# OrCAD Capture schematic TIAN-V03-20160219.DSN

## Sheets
1 03_MIPS_76K_CPU: size A; title: 03_MIPS_76K_CPU; rev: 03; note: Tian
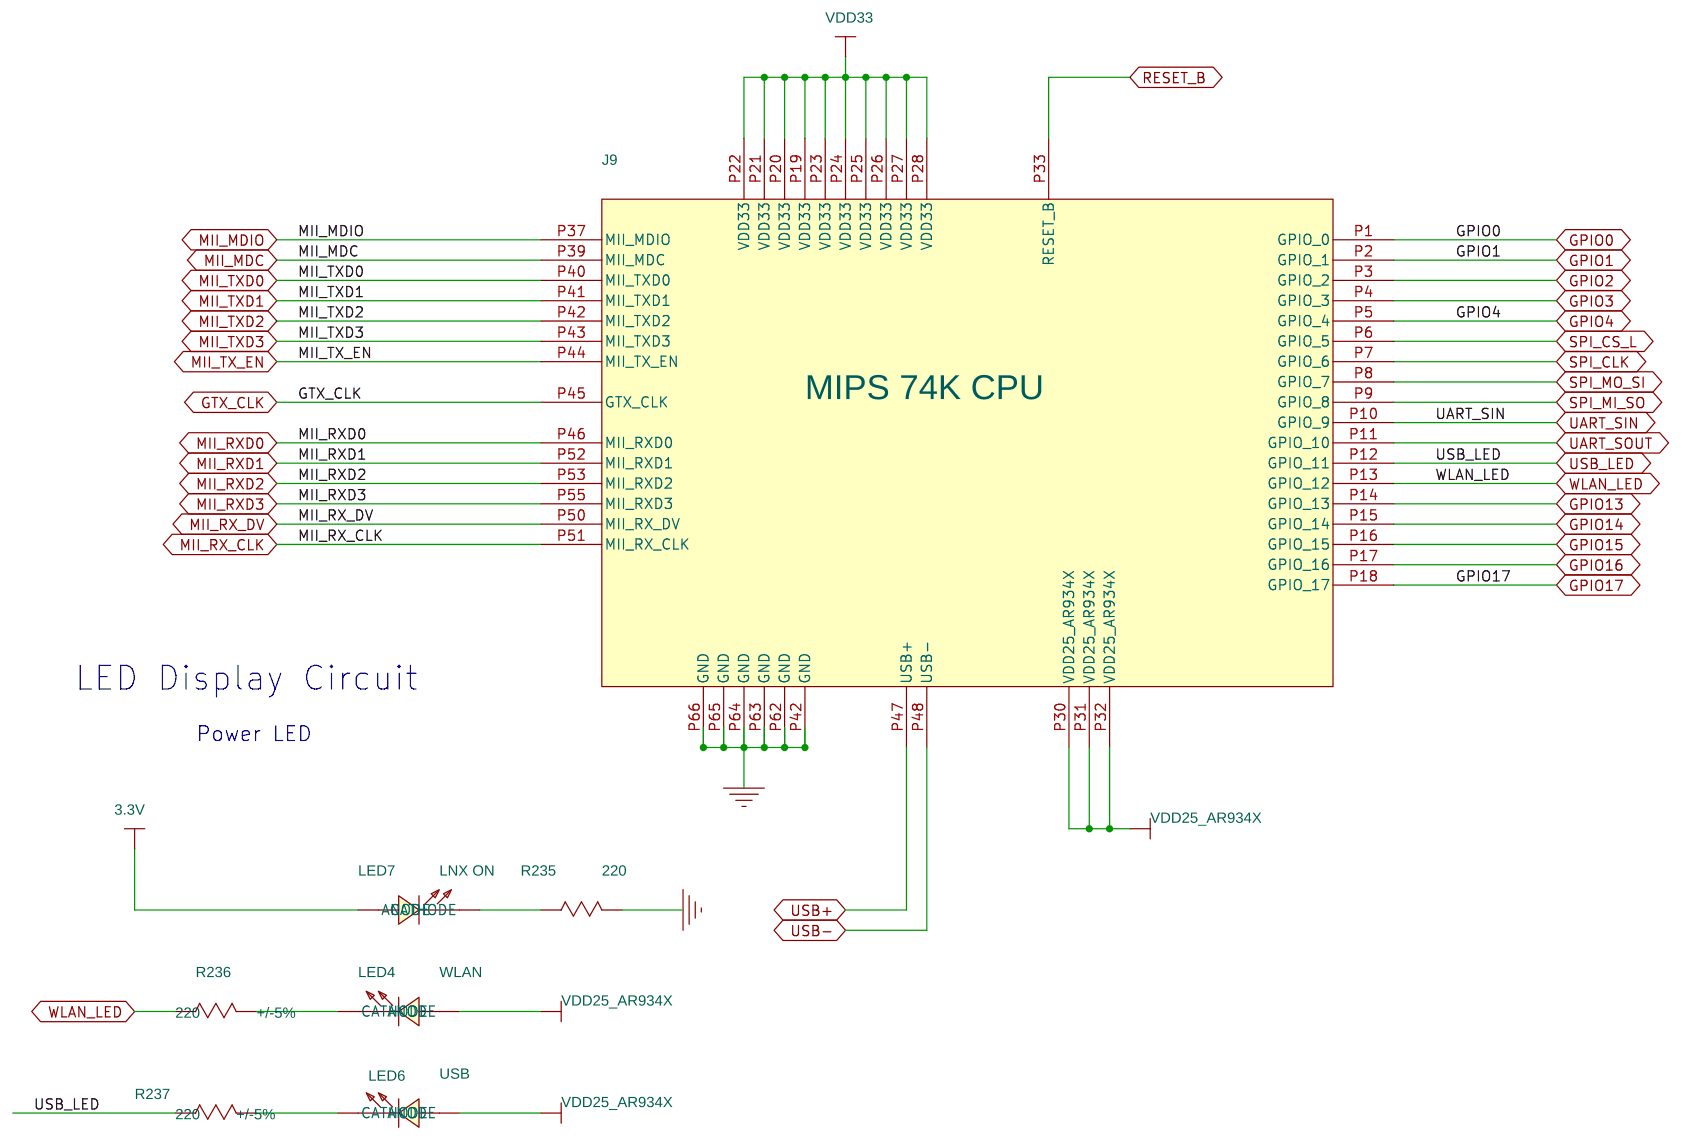
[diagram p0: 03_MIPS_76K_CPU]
2 01_Block_Diagram: title: 01_Block Diagram
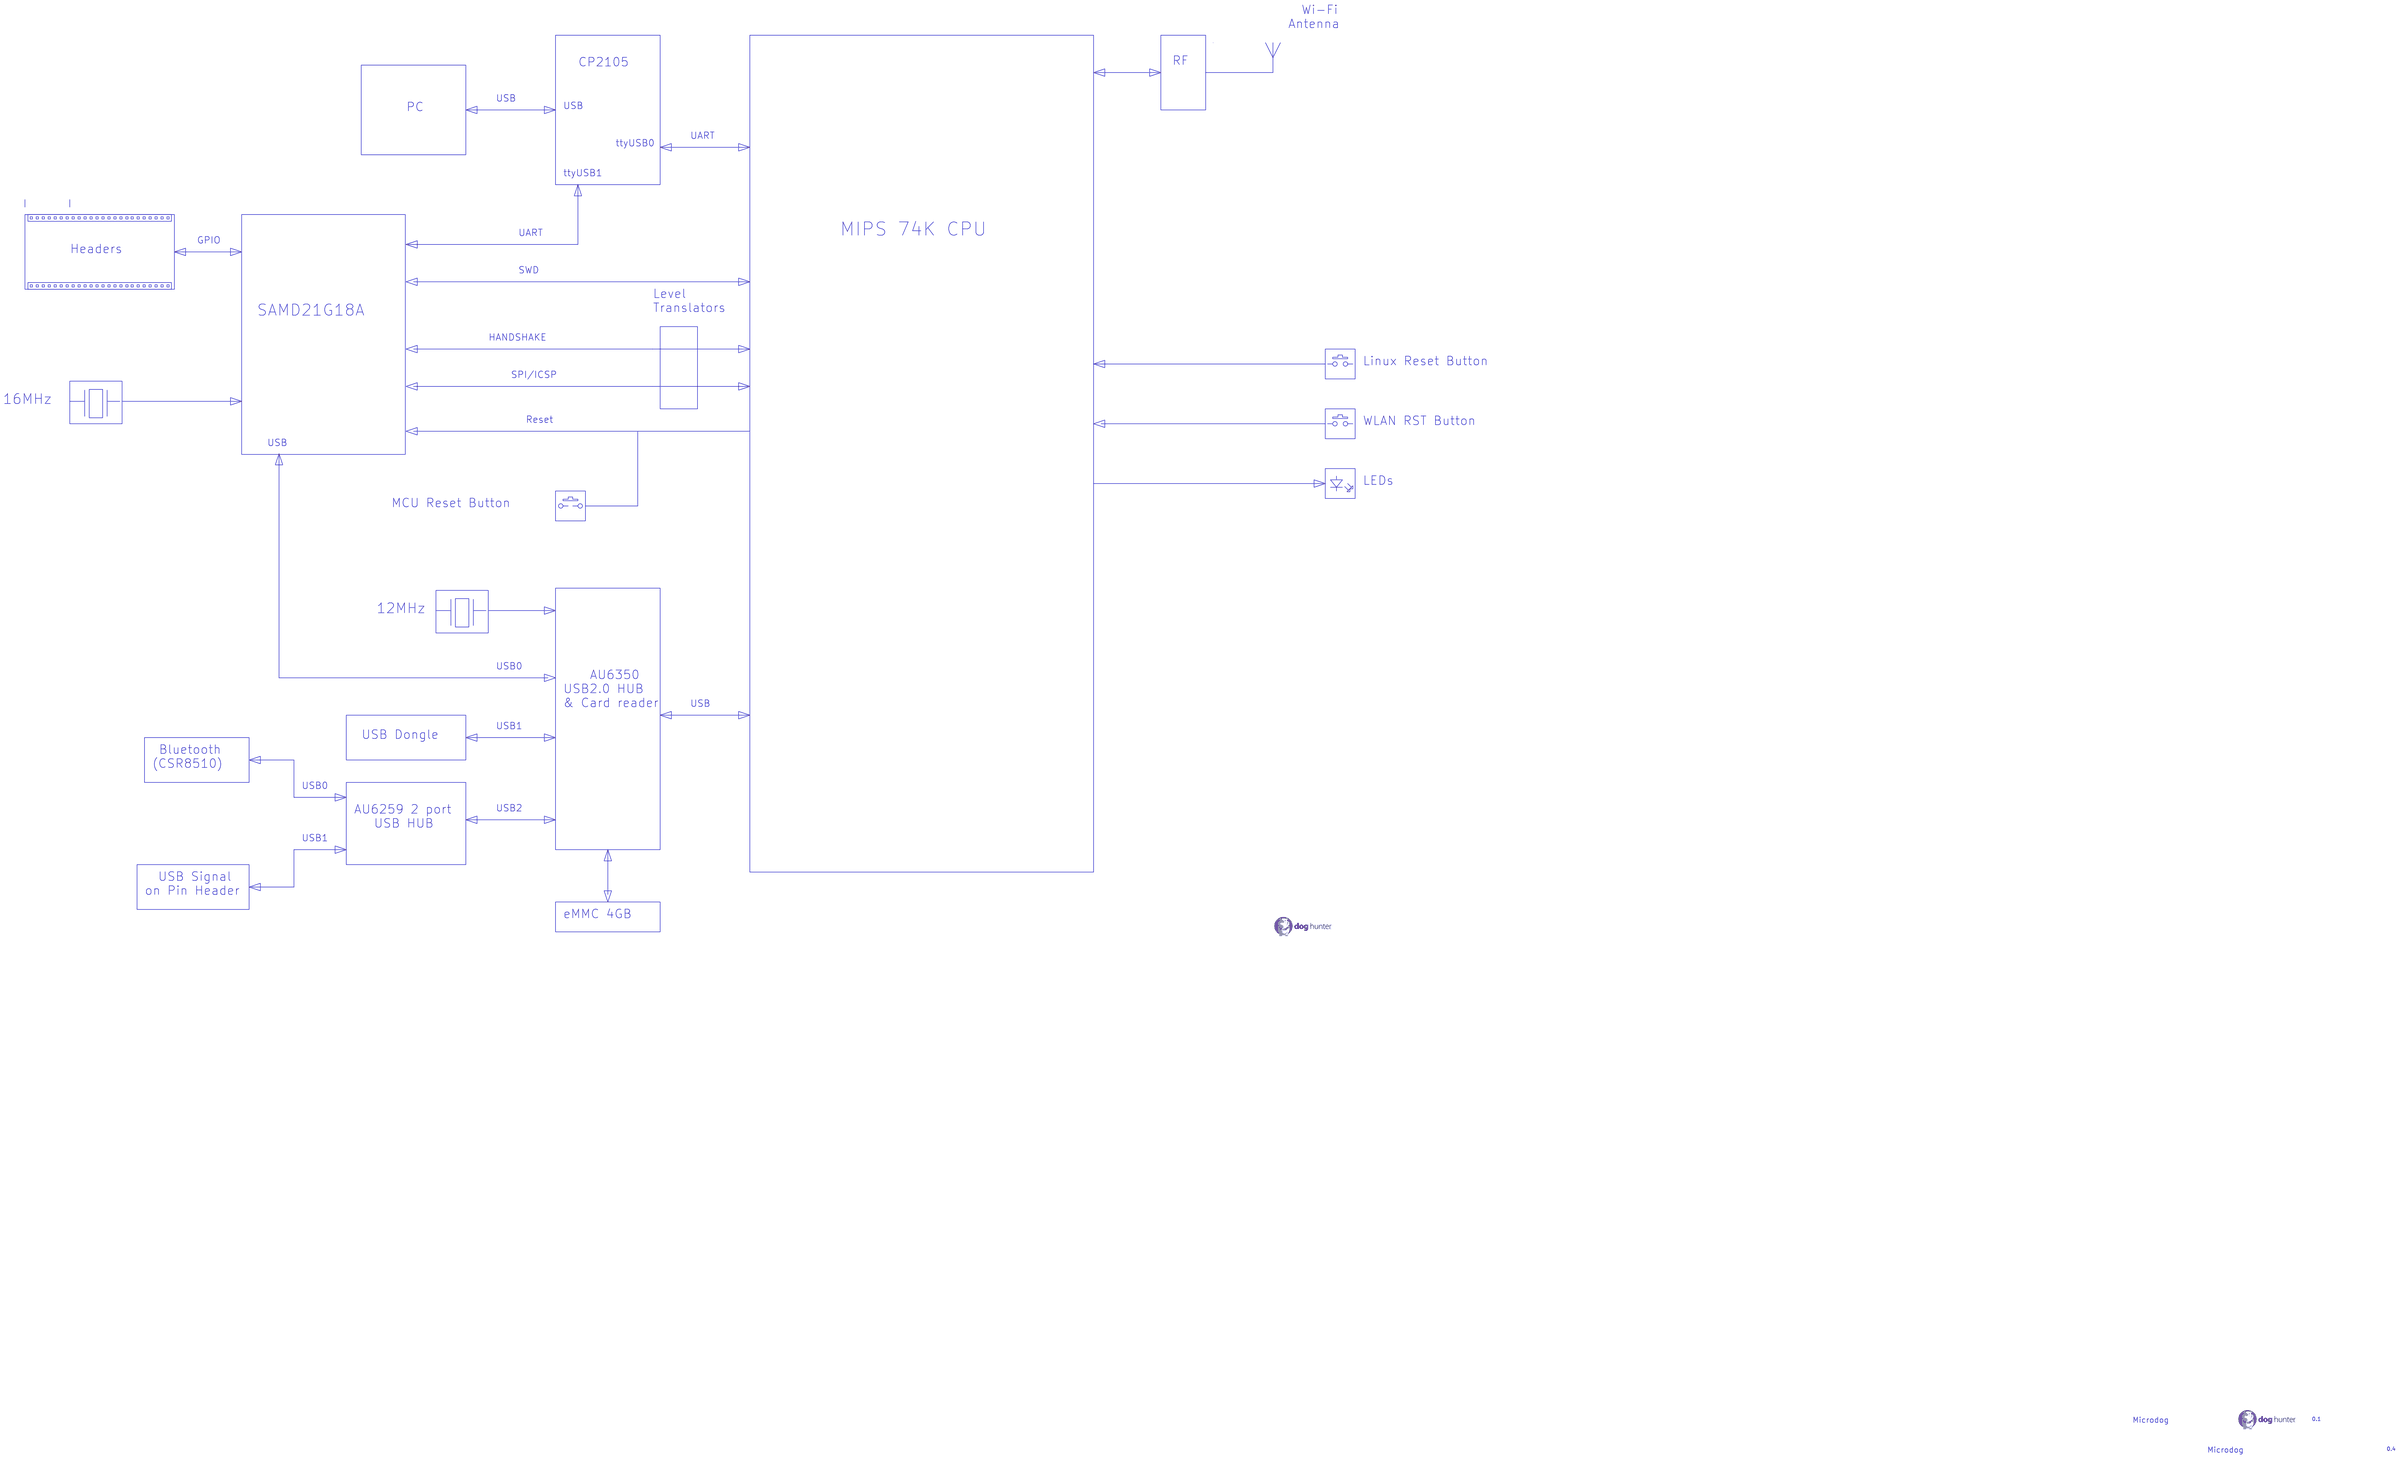
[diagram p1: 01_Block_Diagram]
3 02_Power_Block_Diagram: size A3; title: 02_Power Block Diagram
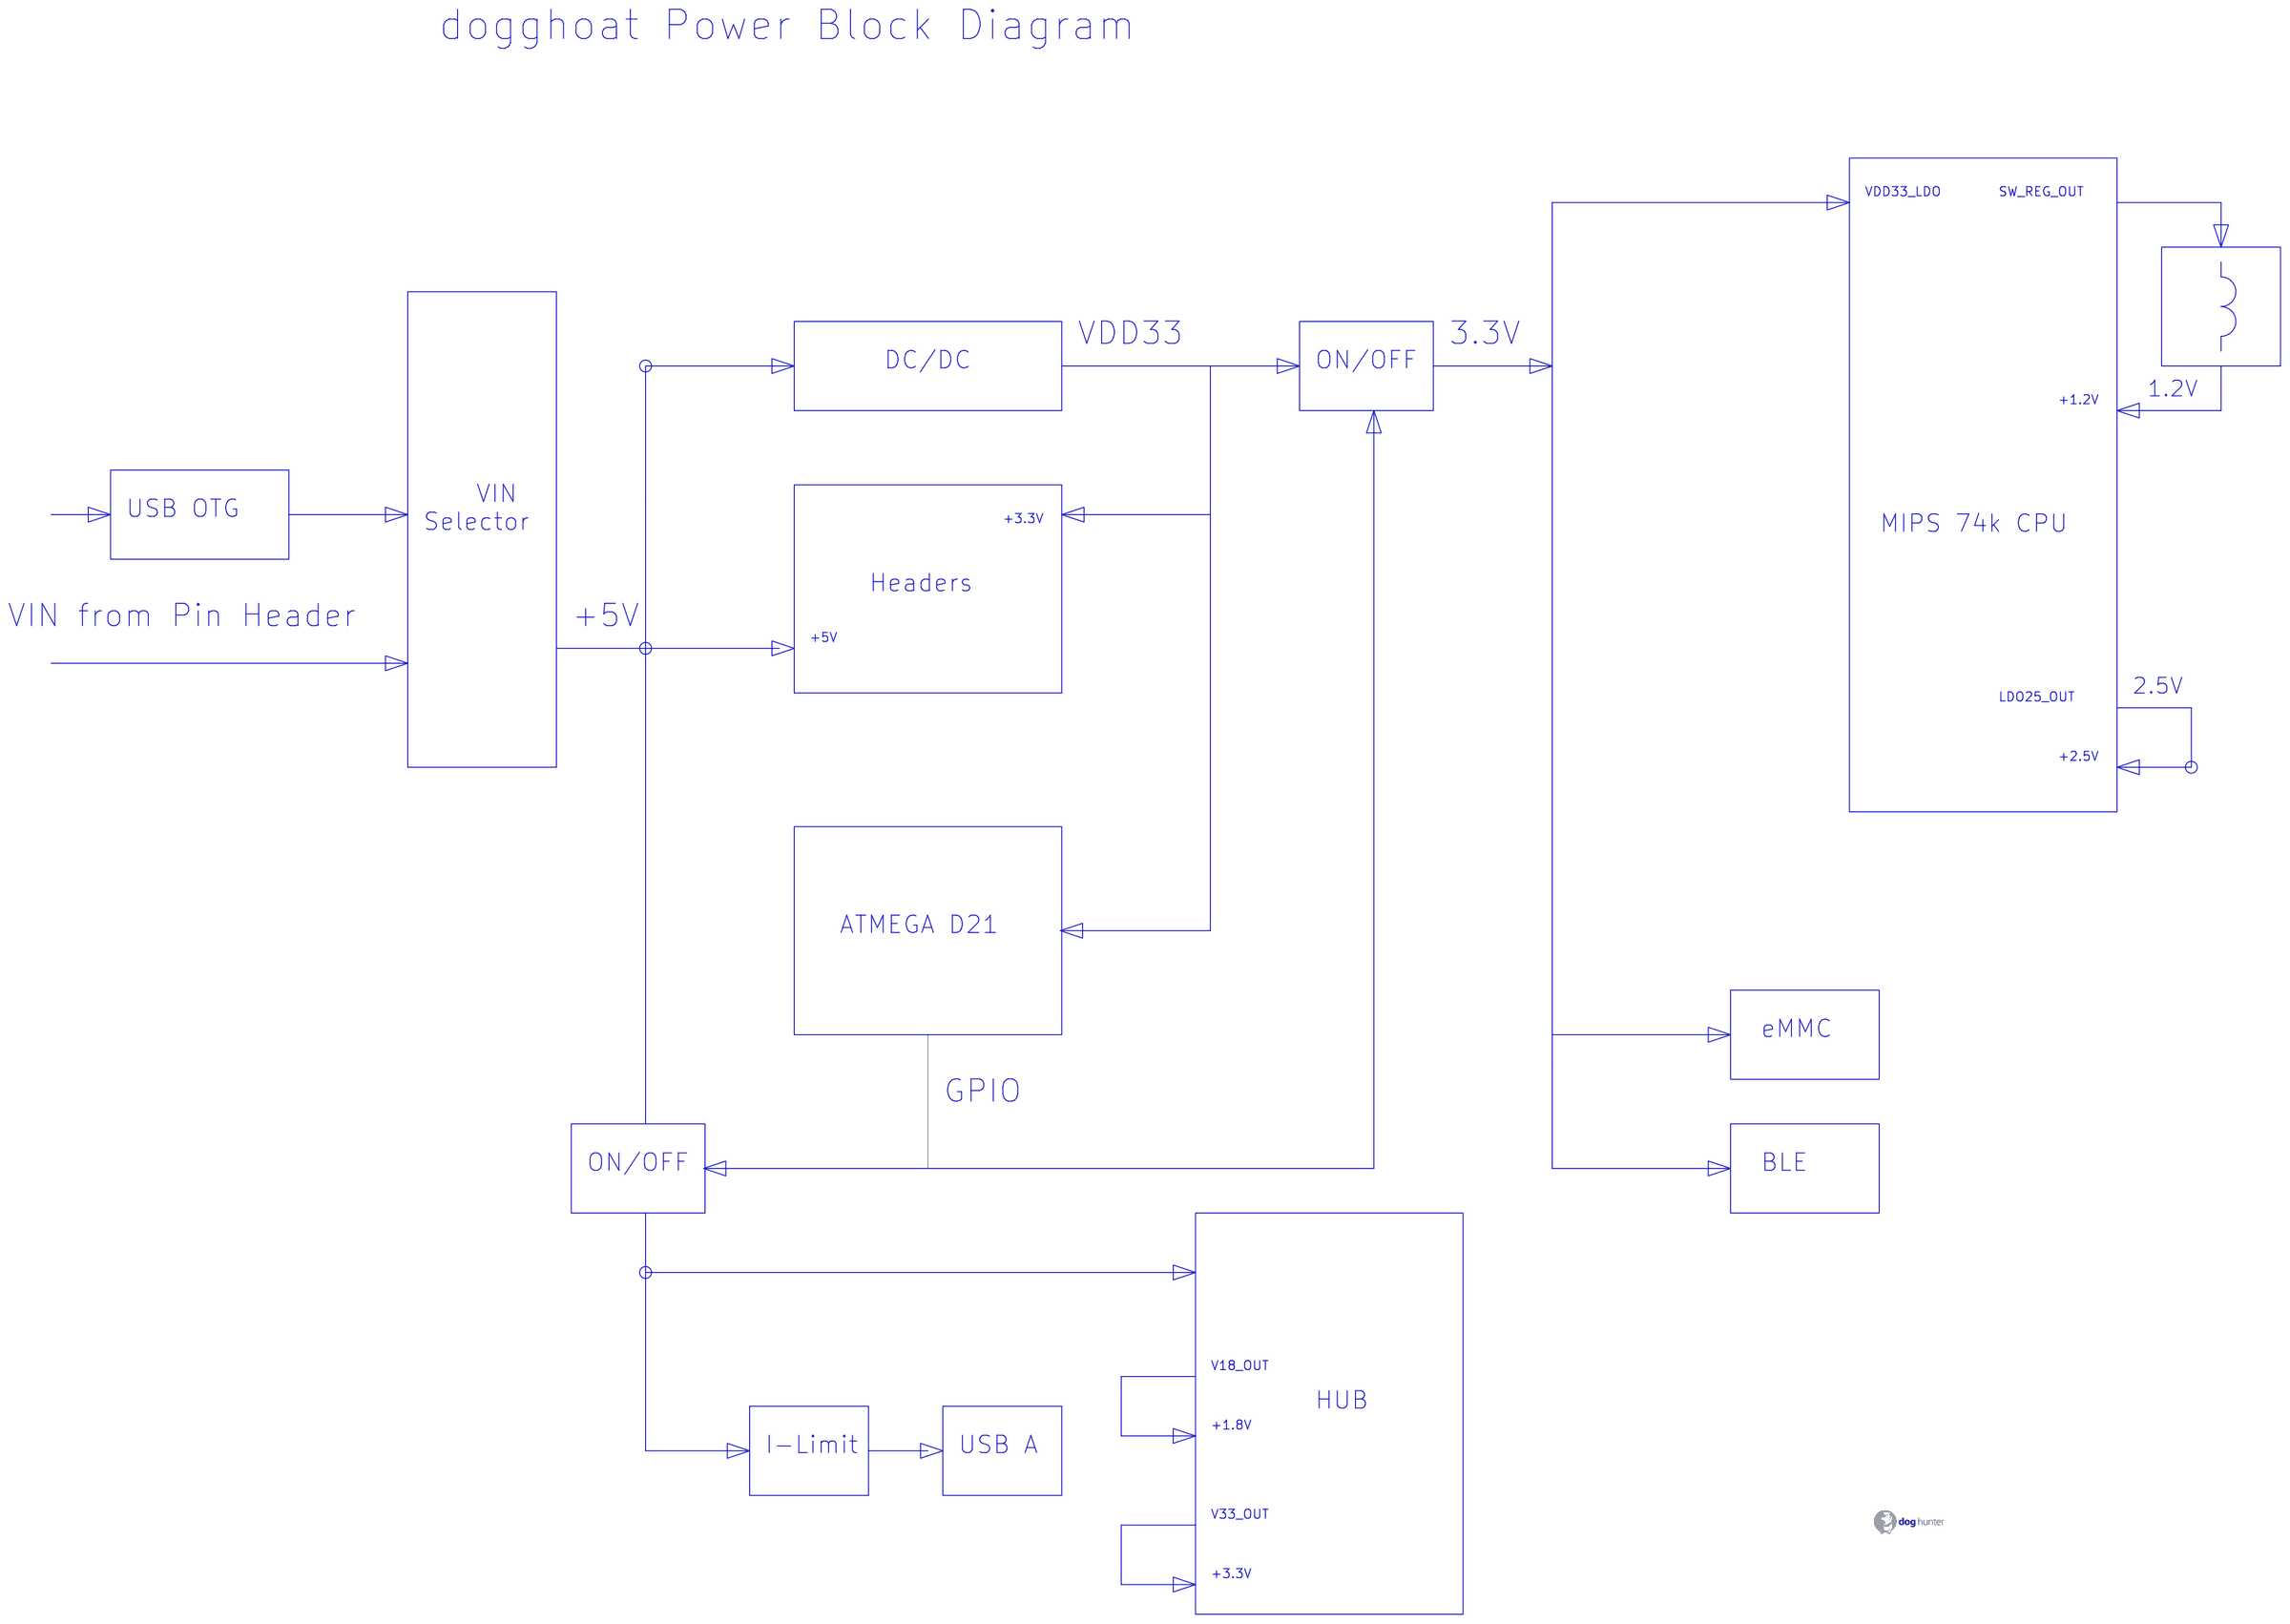
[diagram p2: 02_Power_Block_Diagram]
4 06_UART_EJTAG_USB_PWR_FLASH: size C; title: 06_UART_EJTAG_USB_PWR_FLASH
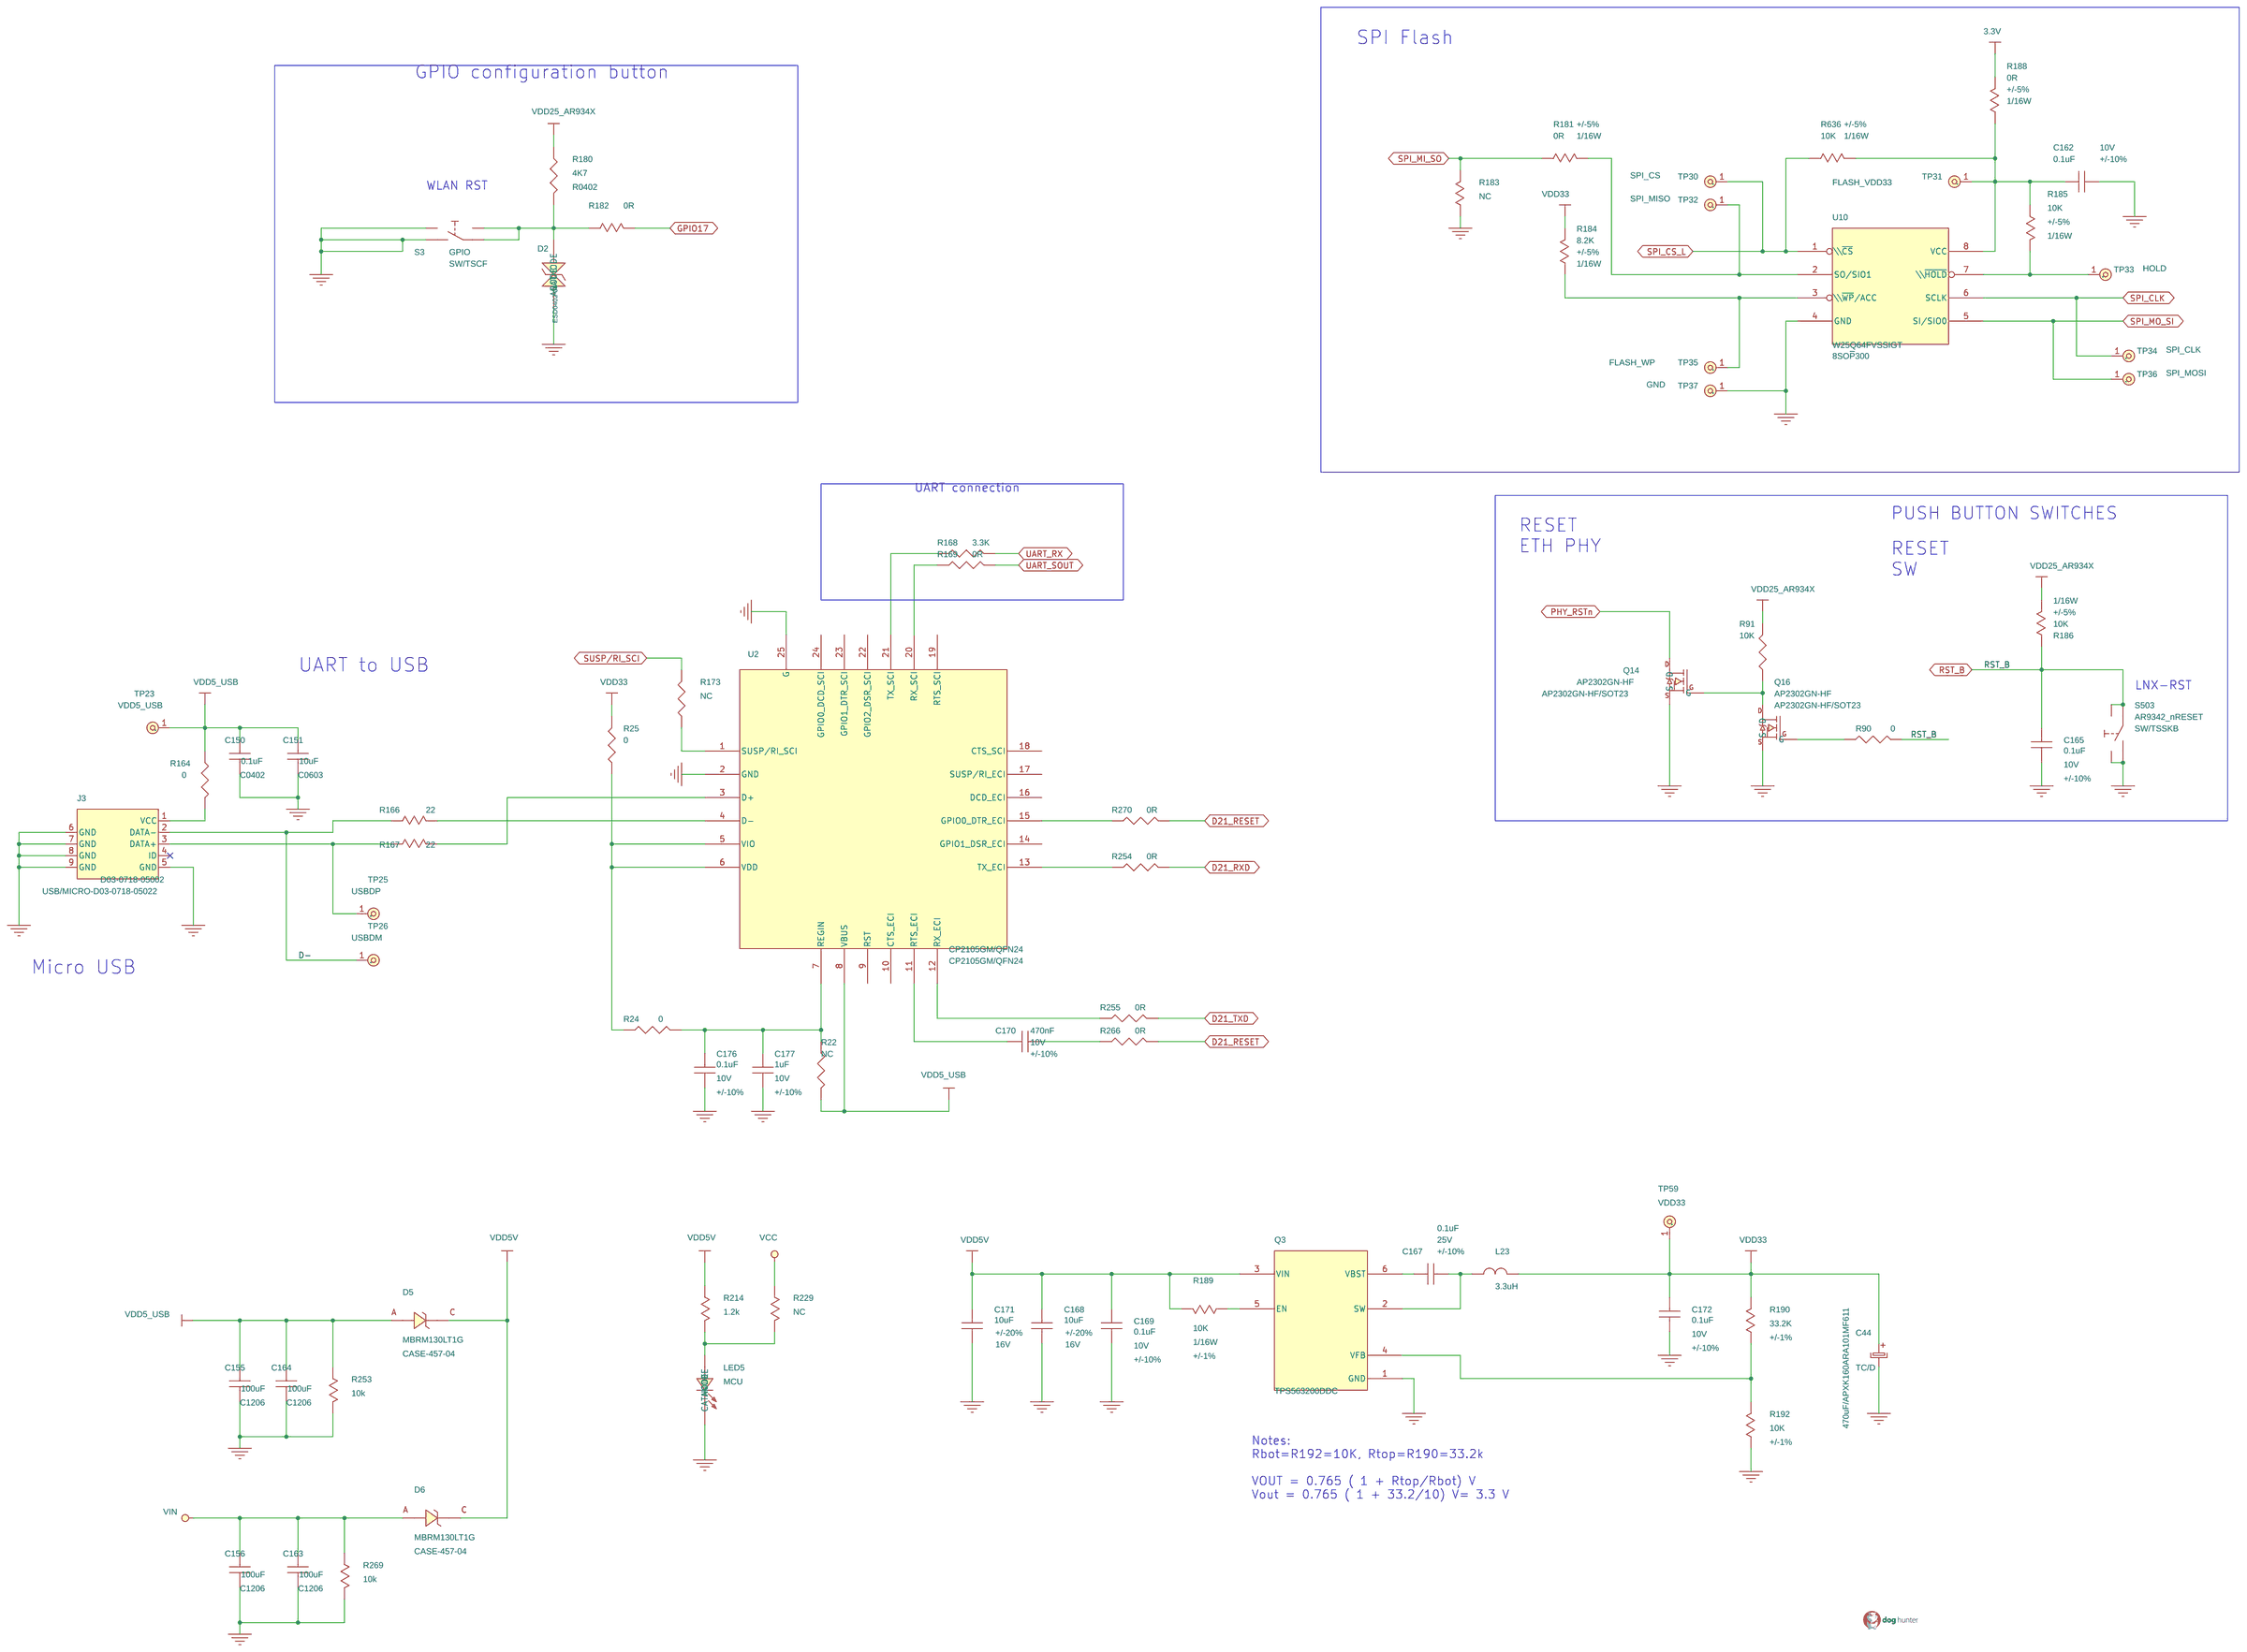
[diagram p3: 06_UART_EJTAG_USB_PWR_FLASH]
5 07_Ethernet_PHY_AR8035: size C; title: 07_Ethernet_PHY_AR8035
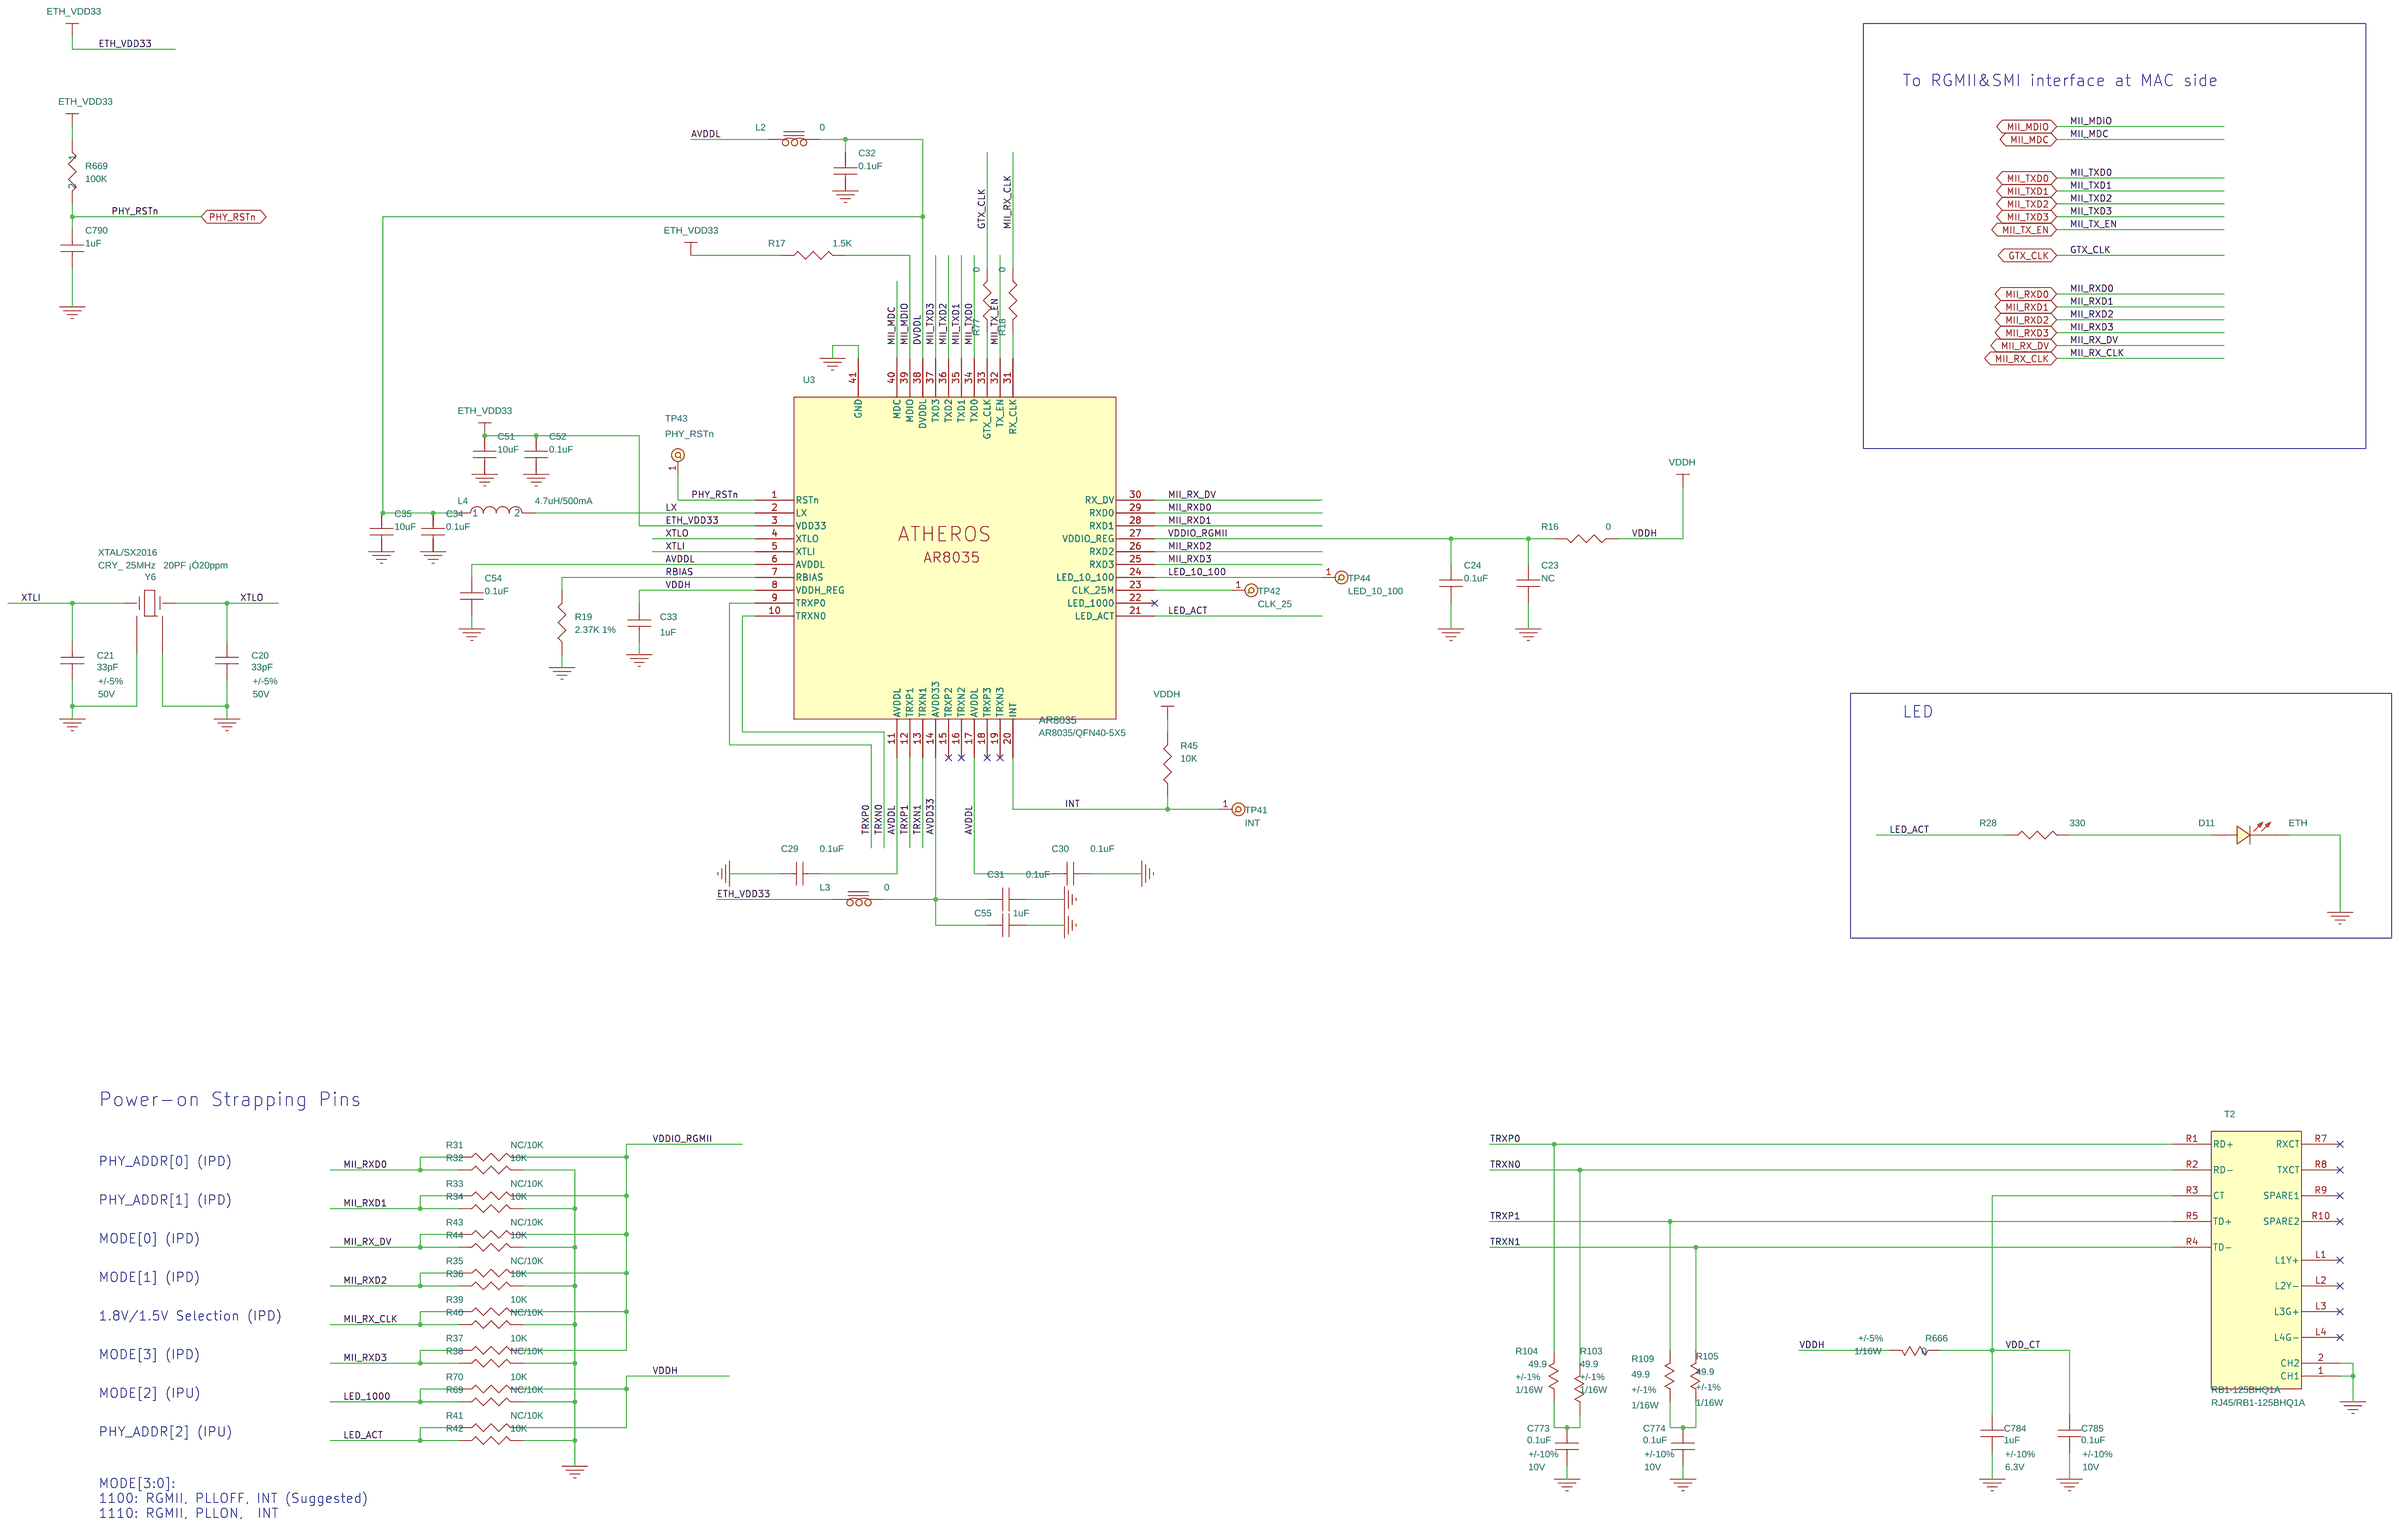
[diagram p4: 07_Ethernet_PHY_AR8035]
6 08_Bluetooth_CSR8510: size B; title: 08_Bluetooth_CSR8510
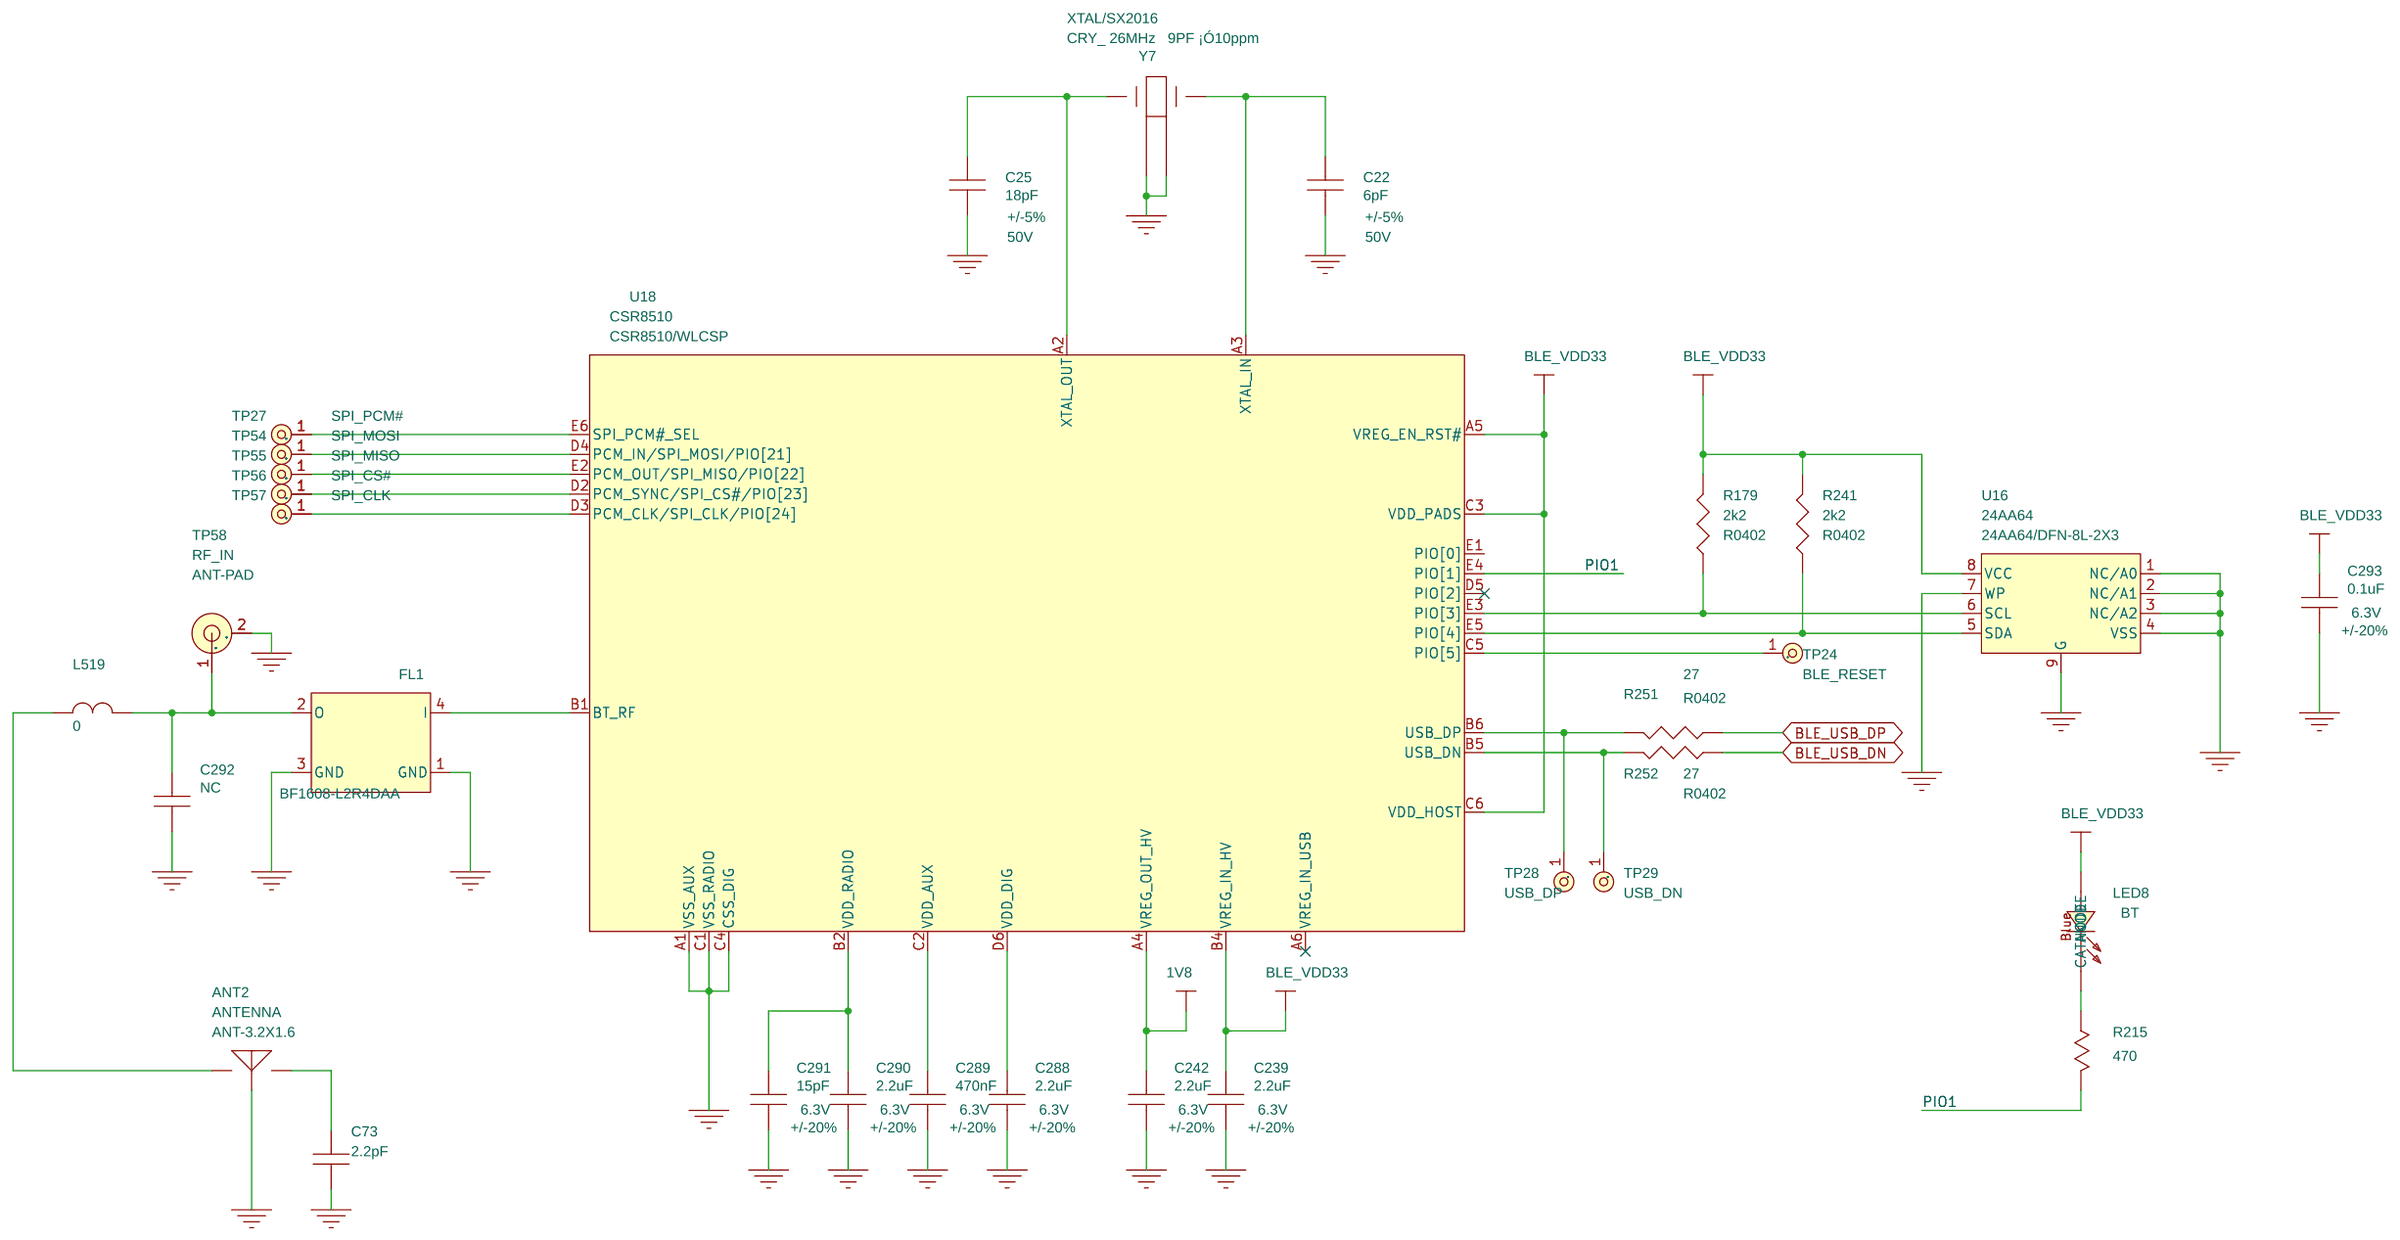
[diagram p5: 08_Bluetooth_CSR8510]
7 09_AU6259: size B; title: 09_AU6259
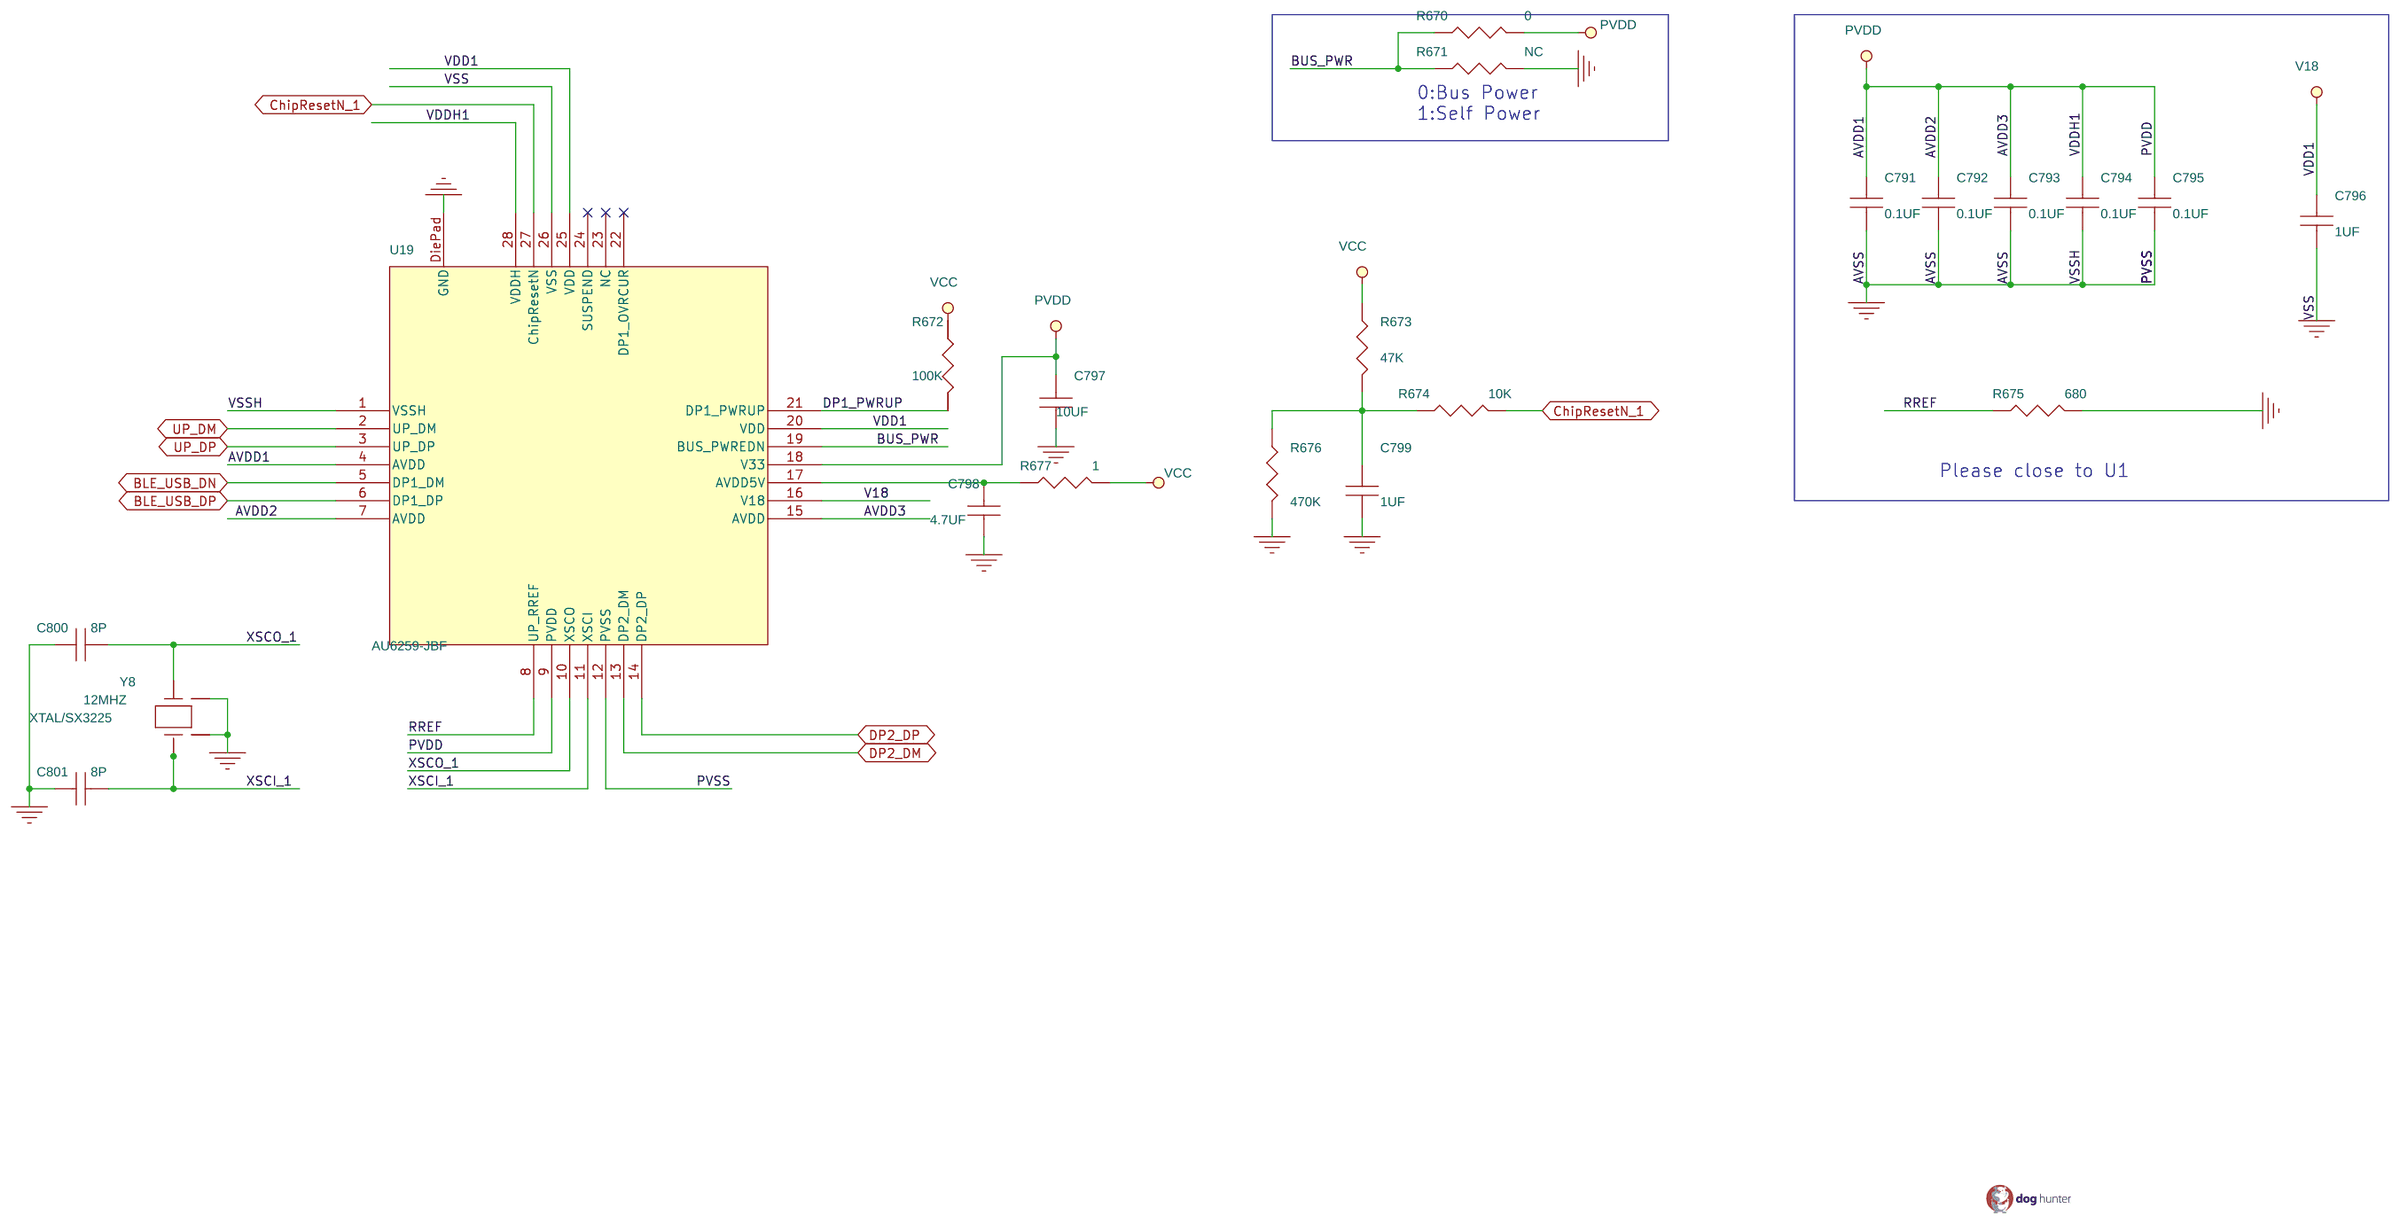
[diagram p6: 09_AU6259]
8 04_SAMD21/LED: size Custom; title: 04_ATmega32U4/LED
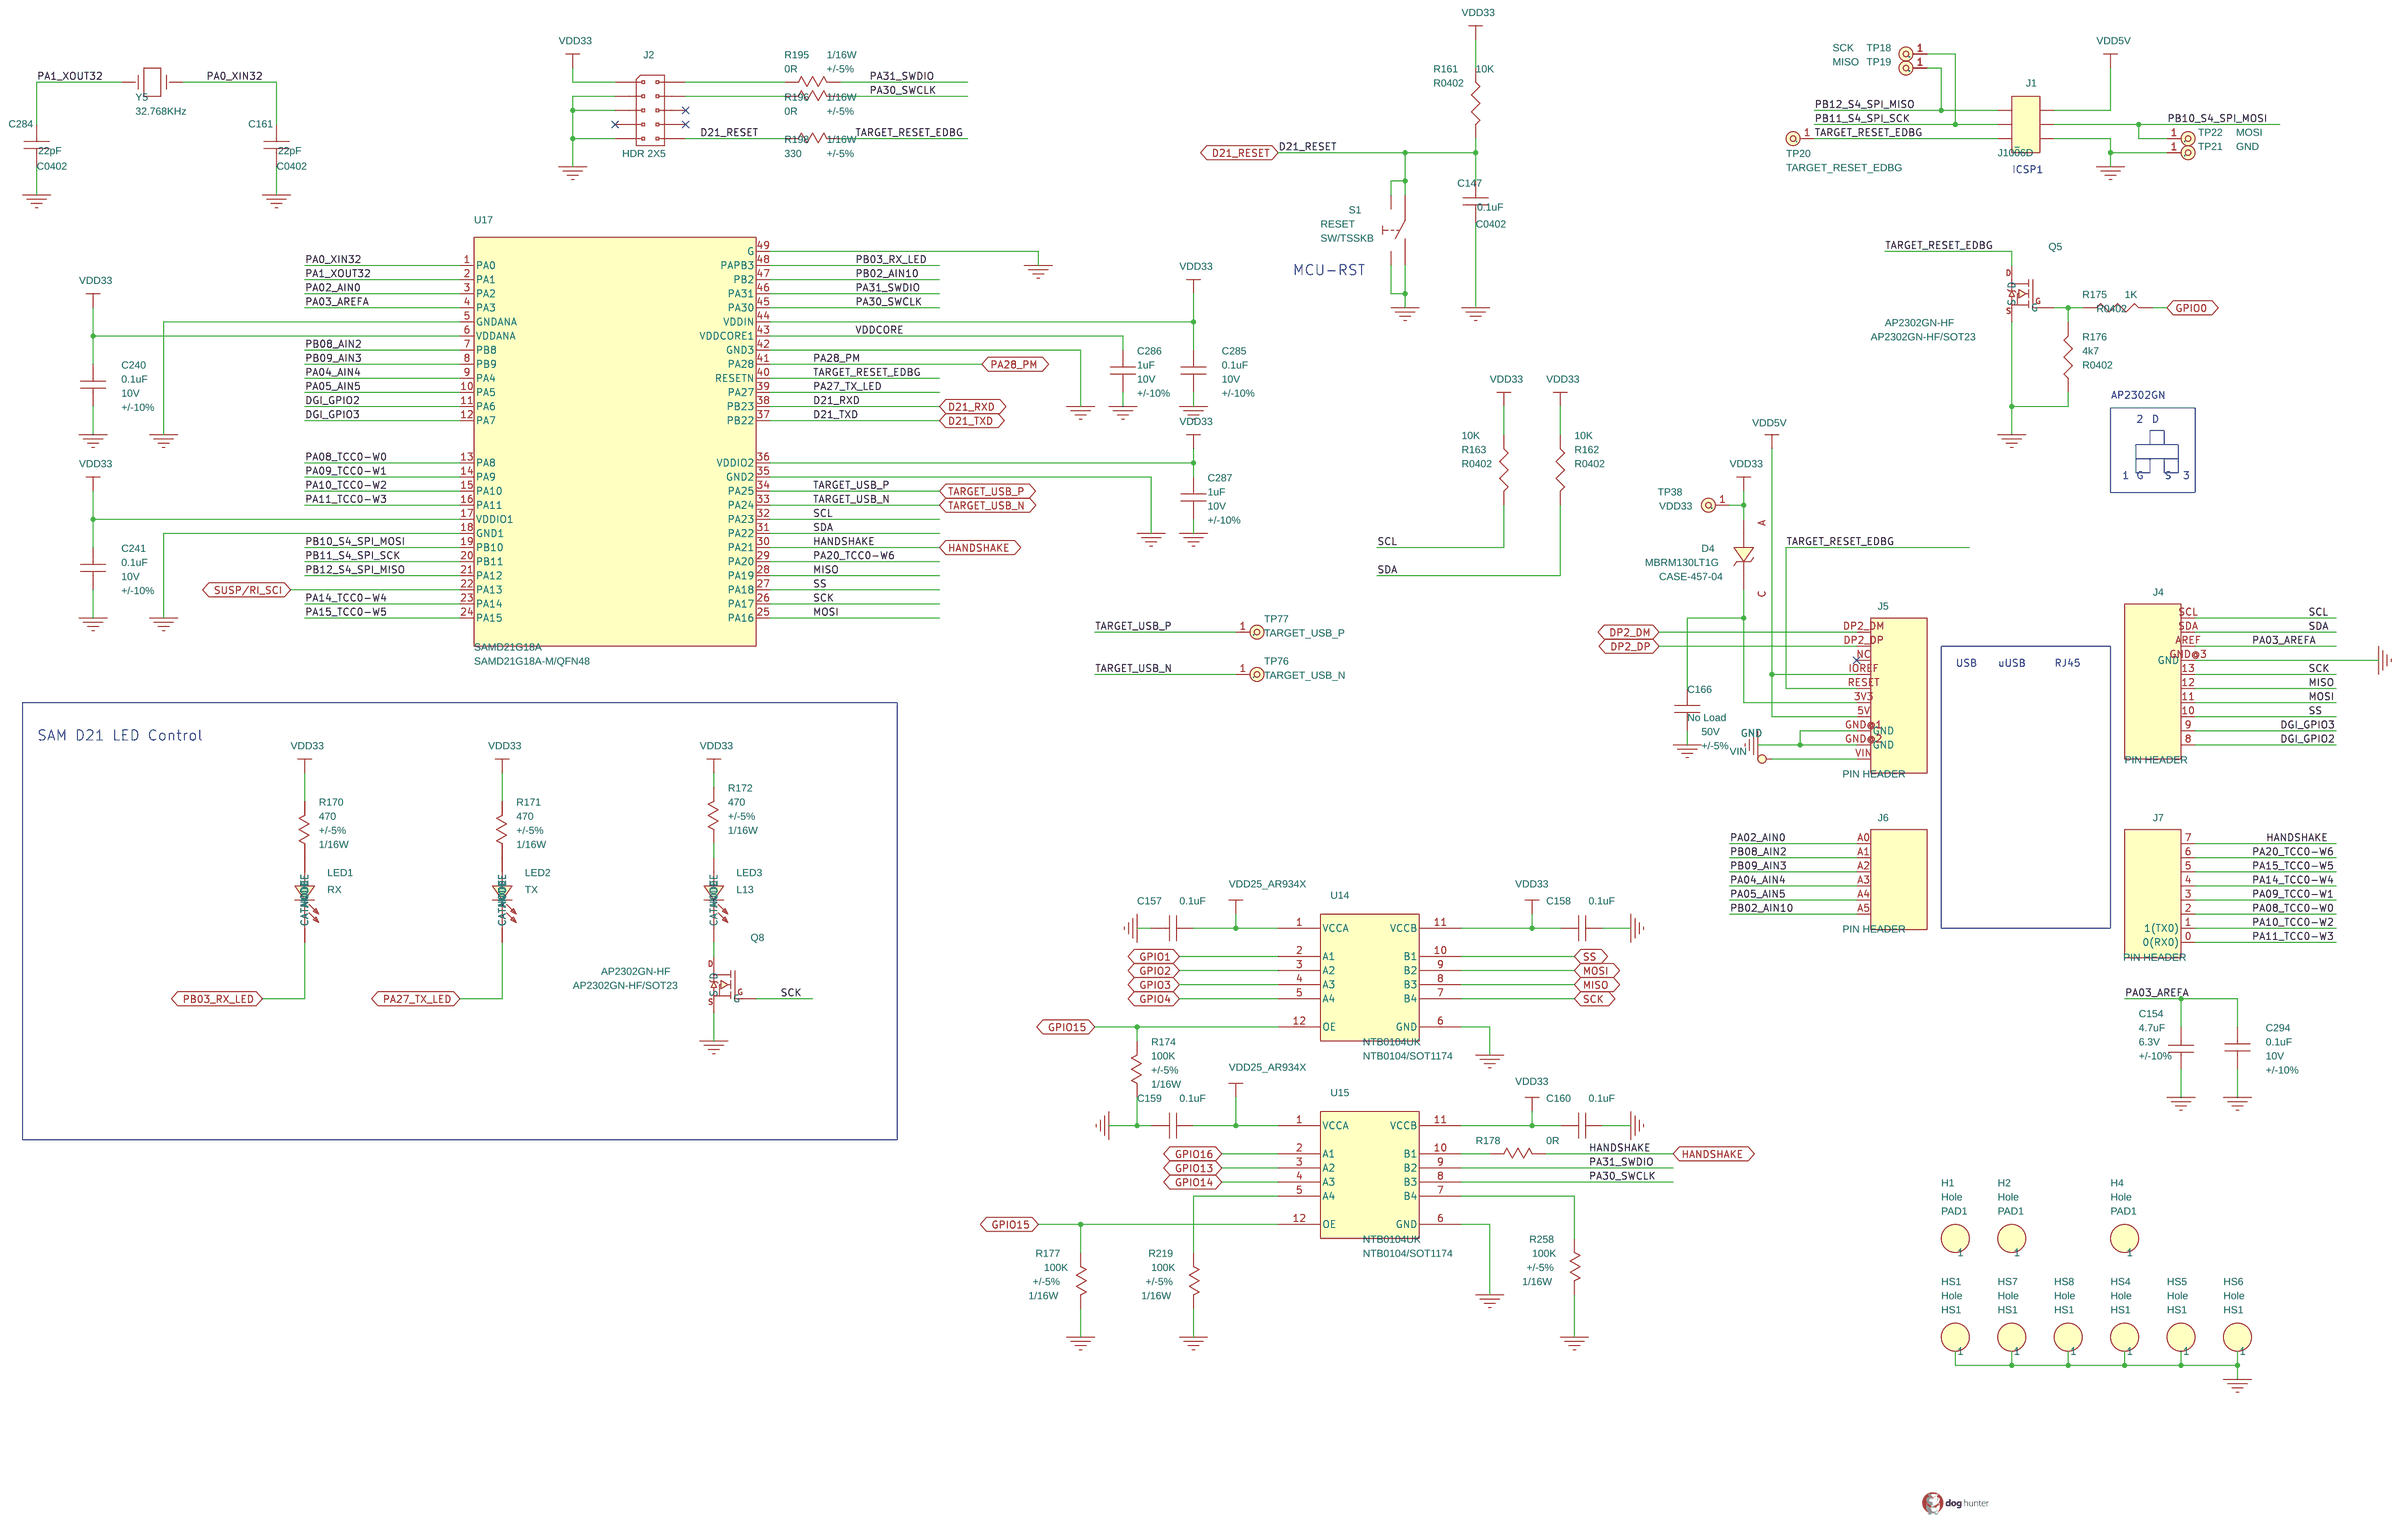
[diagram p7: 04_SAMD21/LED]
9 05_AU6350/eMMC/USB_A Female: size Custom; title: 05_AU6350/eMMC/USB_A Female
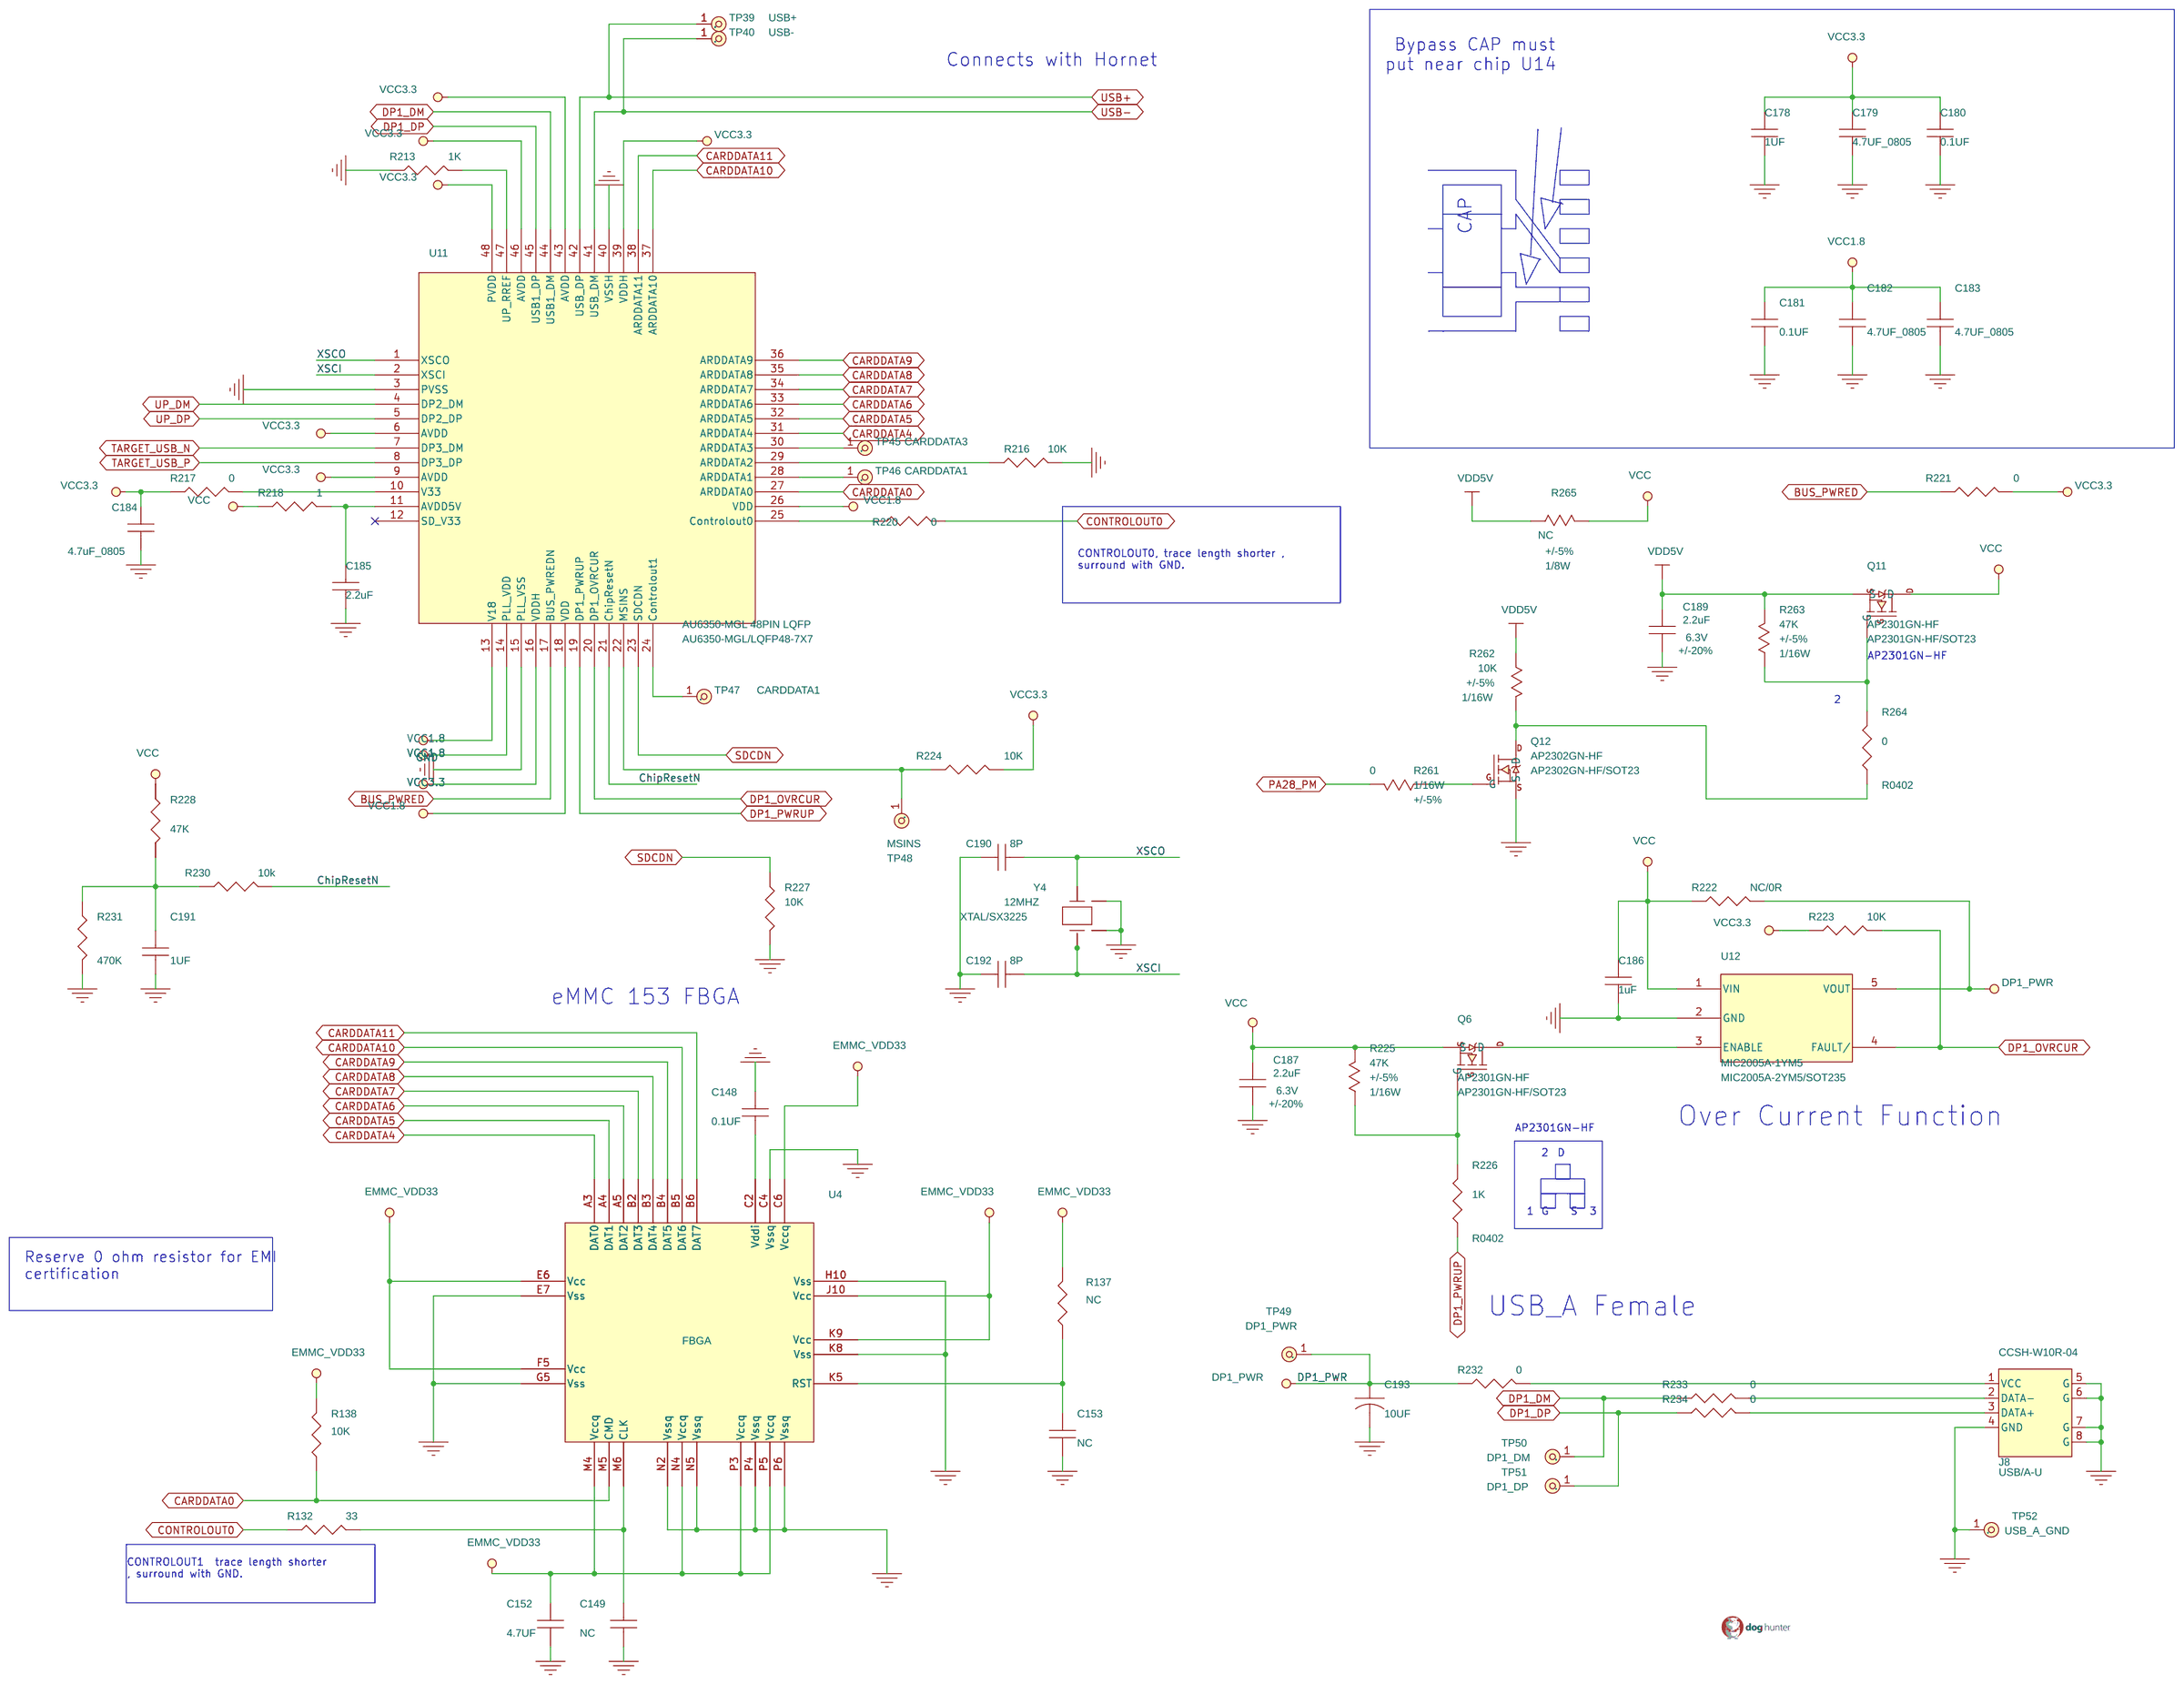
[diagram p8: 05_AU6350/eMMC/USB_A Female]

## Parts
sheet 03_MIPS_76K_CPU
J9  MIPS 74K CPU  [MODULE_74P]
LED4  WLAN  [LED0603]
LED6  USB  [LED0603]
LED7  LNX ON  [LED0603]
R235  220  [R0402]
R236  220  [R0402]
R237  220  [R0402]
sheet 04_SAMD21/LED
C147  0.1uF  [C0402]
C154  4.7uF  [C0603]
C157  0.1uF  [C0402]
C158  0.1uF  [C0402]
C159  0.1uF  [C0402]
C160  0.1uF  [C0402]
C161  22pF  [C0402]
C166  No Load  [C0402]
C240  0.1uF  [C0402]
C241  0.1uF  [C0402]
C284  22pF  [C0402]
C285  0.1uF  [C0402]
C286  1uF  [C0402]
C287  1uF  [C0402]
C294  0.1uF  [C0402]
D4  MBRM130LT1G  [CASE-457-04]
H1  Hole  [PAD1]
H2  Hole  [PAD1]
H4  Hole  [PAD1]
HS1  Hole  [HS1]
HS4  Hole  [HS1]
HS5  Hole  [HS1]
HS6  Hole  [HS1]
HS7  Hole  [HS1]
HS8  Hole  [HS1]
J1  Pitch 2.54 mm  [J100\6D]
J2  STRIP_1.27MM_VERT_PTH_5X2  [J50/10D]
J4  PIN HEADER  [PIN-HEADERX4_D]
J5  PIN HEADER  [PIN-HEADERX4_A]
J6  PIN HEADER  [PIN-HEADERX4_B]
J7  PIN HEADER  [PIN-HEADERX4_C]
LED1  RX  [LED0603]
LED2  TX  [LED0603]
LED3  L13  [LED0603]
Q5  AP2302GN-HF  [AP2302GN-HF/SOT23]
Q8  AP2302GN-HF  [AP2302GN-HF/SOT23]
R161  10K  [R0402]
R162  10K  [R0402]
R163  10K  [R0402]
R170  470  [R0402]
R171  470  [R0402]
R172  470  [R0402]
R174  100K  [R0402]
R175  1K  [R0402]
R176  4k7  [R0402]
R177  100K  [R0402]
R178  0R  [R0402]
R195  0R  [R0402]
R196  0R  [R0402]
R198  330  [R0402]
R219  100K  [R0402]
R258  100K  [R0402]
S1  RESET  [SW/TSSKB]
TP18  SCK  [PADA]
TP19  MISO  [PADA]
TP20  TARGET_RESET_EDBG  [PADA]
TP21  GND  [PADA]
TP22  MOSI  [PADA]
TP38  VDD33  [PADA]
TP76  TARGET_USB_N  [PADA]
TP77  TARGET_USB_P  [PADA]
U14  NTB0104UK  [NTB0104/SOT1174]
U15  NTB0104UK  [NTB0104/SOT1174]
U17  SAMD21G18A  [SAMD21G18A-M/QFN48]
Y5  32.768KHz  [XTAL/S2012R]
sheet 05_AU6350/eMMC/USB_A Female
C148  0.1UF  [C0402]
C149  NC  [C0402]
C152  4.7UF  [C0603]
C153  NC  [C0402]
C178  1UF  [C0402]
C179  4.7UF_0805  [C0805]
C180  0.1UF  [C0402]
C181  0.1UF  [C0402]
C182  4.7UF_0805  [C0805]
C183  4.7UF_0805  [C0805]
C184  4.7uF_0805  [C0805]
C185  2.2uF  [C0402]
C186  1uF  [C0402]
C187  2.2uF  [C0402]
C189  2.2uF  [C0402]
C190  8P  [C0402]
C191  1UF  [C0402]
C192  8P  [C0402]
C193  10UF  [C0603]
J8  CCSH-W10R-04  [USB/A-U]
Q6  AP2301GN-HF  [AP2301GN-HF/SOT23]
Q11  AP2301GN-HF  [AP2301GN-HF/SOT23]
Q12  AP2302GN-HF  [AP2302GN-HF/SOT23]
R132  33  [R0402]
R137  NC  [R0402]
R138  10K  [R0402]
R213  1K  [R0402]
R216  10K  [R0402]
R217  0  [R0402]
R218  1  [R0603]
R220  0  [R0402]
R221  0  [R0402]
R222  NC/0R  [R0402]
R223  10K  [R0402]
R224  10K  [R0402]
R225  47K  [R0402]
R226  1K  [R0402]
R227  10K  [R0402]
R228  47K  [R0402]
R230  10k  [R0402]
R231  470K  [R0402]
R232  0  [R0402]
R233  0  [R0402]
R234  0  [R0402]
R261  0  [R0402]
R262  10K  [R0402]
R263  47K  [R0402]
R264  0  [R0402]
R265  NC  [R0805]
TP39  USB+  [PADA]
TP40  USB-  [PADA]
TP45  CARDDATA3  [PADA]
TP46  CARDDATA1  [PADA]
TP47  CARDDATA1  [PADA]
TP48  MSINS  [PADA]
TP49  DP1_PWR  [PADA]
TP50  DP1_DM  [PADA]
TP51  DP1_DP  [PADA]
TP52  USB_A_GND  [PADA]
U4  FBGA  [VFBGA-11.5X13X1-153P]
U11  AU6350-MGL 48PIN LQFP  [AU6350-MGL/LQFP48-7X7]
U12  MIC2005A-1YM5  [MIC2005A-2YM5/SOT235]
Y4  12MHZ  [XTAL/SX3225]
sheet 06_UART_EJTAG_USB_PWR_FLASH
C44  470uF/APXK160ARA101MF611  [TC/D]
C150  0.1uF  [C0402]
C151  10uF  [C0603]
C155  100uF  [C1206]
C156  100uF  [C1206]
C162  0.1uF  [C0402]
C163  100uF  [C1206]
C164  100uF  [C1206]
C165  0.1uF  [C0402]
C167  0.1uF  [C0402]
C168  10uF  [C0805]
C169  0.1uF  [C0402]
C170  470nF  [C0402]
C171  10uF  [C0805]
C172  0.1uF  [C0402]
C176  0.1uF  [C0402]
C177  1uF  [C0402]
D2  ESD0402-06  [ESD0402]
D5  MBRM130LT1G  [CASE-457-04]
D6  MBRM130LT1G  [CASE-457-04]
J3  D03-0718-05002  [USB/MICRO-D03-0718-05022]
L23  3.3uH  [TMPC0402HP-3R3MG-Z02]
LED5  MCU  [LED0603]
Q3  TPS563200DDC  [TPS563200DDC]
Q14  AP2302GN-HF  [AP2302GN-HF/SOT23]
Q16  AP2302GN-HF  [AP2302GN-HF/SOT23]
R22  NC  [R0402]
R24  0  [R0402]
R25  0  [R0402]
R90  0  [R0402]
R91  10K  [R0402]
R164  0  [R0805]
R166  22  [R0402]
R167  22  [R0402]
R168  3.3K  [R0402]
R169  0R  [R0402]
R173  NC  [R0402]
R180  4K7  [R0402]
R181  0R  [R0402]
R182  0R  [R0402]
R183  NC  [R0402]
R184  8.2K  [R0402]
R185  10K  [R0402]
R186  10K  [R0402]
R188  0R  [R0402]
R189  10K  [R0402]
R190  33.2K  [R0402]
R192  10K  [R0402]
R214  1.2k  [R0402]
R229  NC  [R0402]
R253  10k  [R0402]
R254  0R  [R0402]
R255  0R  [R0402]
R266  0R  [R0402]
R269  10k  [R0402]
R270  0R  [R0402]
R636  10K  [R0402]
S3  GPIO  [SW/TSCF]
S503  AR9342_nRESET  [SW/TSSKB]
TP23  VDD5_USB  [PADA]
TP25  USBDP  [PADA]
TP26  USBDM  [PADA]
TP30  SPI_CS  [PADA]
TP31  FLASH_VDD33  [PADA]
TP32  SPI_MISO  [PADA]
TP33  HOLD  [PADA]
TP34  SPI_CLK  [PADA]
TP35  FLASH_WP  [PADA]
TP36  SPI_MOSI  [PADA]
TP37  GND  [PADA]
TP59  VDD33  [PADA]
U2  CP2105GM/QFN24  [CP2105GM/QFN24]
U10  W25Q64FVSSIGT  [8SOP\300]
sheet 07_Ethernet_PHY_AR8035
C20  33pF  [C0201]
C21  33pF  [C0201]
C23  NC  [C0402]
C24  0.1uF  [C0402]
C29  0.1uF  [C0402]
C30  0.1uF  [C0402]
C31  0.1uF  [C0402]
C32  0.1uF  [C0402]
C33  1uF  [C0402]
C34  0.1uF  [C0402]
C35  10uF  [C0603]
C51  10uF  [C0603]
C52  0.1uF  [C0402]
C54  0.1uF  [C0402]
C55  1uF  [C0402]
C773  0.1uF  [C0402]
C774  0.1uF  [C0402]
C784  1uF  [C0402]
C785  0.1uF  [C0402]
C790  1uF  [C0402]
D11  ETH  [led0603]
L2  0  [L0603]
L3  0  [L0603]
L4  4.7uH/500mA  [L/C3-P1.2R]
R16  0  [R0805]
R17  1.5K  [R0402]
R18  0  [R0603]
R19  2.37K 1%  [R0402]
R28  330  [R0402]
R31  NC/10K  [R0603]
R32  10K  [R0402]
R33  NC/10K  [R0603]
R34  10K  [R0402]
R35  NC/10K  [R0603]
R36  10K  [R0402]
R37  10K  [R0402]
R38  NC/10K  [R0603]
R39  10K  [R0402]
R40  NC/10K  [R0603]
R41  NC/10K  [R0603]
R42  10K  [R0402]
R43  NC/10K  [R0603]
R44  10K  [R0402]
R45  10K  [R0402]
R69  NC/10K  [R0603]
R70  10K  [R0402]
R77  0  [R0603]
R103  49.9  [R0402]
R104  49.9  [R0402]
R105  49.9  [R0402]
R109  49.9  [R0402]
R666  0  [R0402]
R669  100K  [R0402]
T2  RB1-125BHQ1A  [RJ45/RB1-125BHQ1A]
TP41  INT  [PADA]
TP42  CLK_25  [PADA]
TP43  PHY_RSTn  [PADA]
TP44  LED_10_100  [PADA]
U3  AR8035  [AR8035/QFN40-5X5]
Y6  CRY_ 25MHz   20PF ¡Ó20ppm  [XTAL/SX2016]
sheet 08_Bluetooth_CSR8510
ANT2  ANTENNA  [ANT-3.2X1.6]
C22  6pF  [C0201]
C25  18pF  [C0201]
C73  2.2pF  [C0402]
C239  2.2uF  [C0402]
C242  2.2uF  [C0402]
C288  2.2uF  [C0402]
C289  470nF  [C0402]
C290  2.2uF  [C0402]
C291  15pF  [C0402]
C292  NC  [C0402]
C293  0.1uF  [C0402]
FL1  BF1608-L2R4DAA  [BF1608-L2R4DAA]
L519  0  [L0402]
LED8  BT  [LED0603]
R179  2k2  [R0402]
R215  470  [R0402]
R241  2k2  [R0402]
R251  27  [R0402]
R252  27  [R0402]
TP24  BLE_RESET  [PADA]
TP27  SPI_PCM#  [PADA]
TP28  USB_DP  [PADA]
TP29  USB_DN  [PADA]
TP54  SPI_MOSI  [PADA]
TP55  SPI_MISO  [PADA]
TP56  SPI_CS#  [PADA]
TP57  SPI_CLK  [PADA]
TP58  RF_IN  [ANT-PAD]
U16  24AA64  [24AA64/DFN-8L-2X3]
U18  CSR8510  [CSR8510/WLCSP]
Y7  CRY_ 26MHz   9PF ¡Ó10ppm  [XTAL/SX2016]
sheet 09_AU6259
C791  0.1UF  [C0402]
C792  0.1UF  [C0402]
C793  0.1UF  [C0402]
C794  0.1UF  [C0402]
C795  0.1UF  [C0402]
C796  1UF  [C0402]
C797  10UF  [C0603]
C798  4.7UF  [C0603]
C799  1UF  [C0402]
C800  8P  [C0402]
C801  8P  [C0402]
R670  0  [R0402]
R671  NC  [R0402]
R672  100K  [R0402]
R673  47K  [R0402]
R674  10K  [R0402]
R675  680  [R0402]
R676  470K  [R0402]
R677  1  [R0402]
U19  AU6259-JBF  [AU6259661-JBF-GR/QFN28]
Y8  12MHZ  [XTAL/SX3225]

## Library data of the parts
J9 = Module_Pin-Out_16
LED4 = LED-0603-LTST-C190GKT_8: AtherosDescription: DIO,LED,GREEN CLEAR,0603,SMD; CISPartType: Diodes\LED
LED6 = LED-0603-LTST-C190GKT_9: AtherosDescription: DIO,LED,GREEN CLEAR,0603,SMD; CISPartType: Diodes\LED
LED7 = LED-0603-LTST-C190GKT_7: AtherosDescription: DIO,LED,GREEN CLEAR,0603,SMD; CISPartType: Diodes\LED
R214 R215 R229 R235 R253 R269 = RES: ATHEROS KEY: 051-221RJ-000; AtherosDescription: RES,0402,220 OHMS,+/-5%,1/16W; CISPartType: Resistor\0402; Tolerance: +/-5%; WATTAGE: ?
R236 R237 = RES: ATHEROS KEY: 051-221RJ-000; AtherosDescription: RES,0402,220 OHMS,+/-5%,1/16W; CISPartType: Resistor\0402; Tolerance: +/-5%; WATTAGE: 1/16W
C147 C149 C795 = CAP_NP
C154 = CAP: ATHEROS KEY: 032-475CK-001; AtherosDescription: CAP,0603,X5R,4.7uF,10%,6.3V; CISPartType: Capacitor\0603; StandardCost-100K: 0; Tolerance: +/-10%; URL: 0; VendorDescription: CAP, MLCC, X5R, 1uF +/-10%, 10V, 0603, 7"T+R; VendorName: Yageo; VendorPart1: 309; VendorPartNumber: CC0603KRX5R6BB105; Voltage: 6.3V
C157-C160 = CAP: ATHEROS KEY: 031-104CK-022; AtherosDescription: CAP,0402,X7R,0.1uF,+/-10%,10V; CISPartType: Capacitor\0402; Tolerance: +/-10%; Voltage: 6.3V
C150 C151 C155 C156 C161 C163 C164 C284 = 27PF_N_0402_5%
C166 = CAP: ATHEROS KEY: 030-100CJ-000; AtherosDescription: CAP,0201,COG,10pF,+/-5%,50V; CISPartType: Capacitor\0201; Tolerance: +/-5%; Voltage: 50V
C169 C170 C172 C176 C177 C240 C241 C285-C287 C294 C773 C774 C785 = CAP: ATHEROS KEY: 031-104CK-002; AtherosDescription: CAP,0402,X5R,0.1uF,+/-10%,10V; CISPartType: Capacitor\0402; Tolerance: +/-10%; Voltage: 10V
D4-D6 = BZX84C22_SOT_4: Foxlink_Description: DIODE,SCHOTTKY,SOD-123,0.5A 40V,MBR0540,FAIRCHILD,RoHS; Foxlink_PN: PN APPLY; PAGE: 17; Vendor: FAIRCHILD
H1 H2 H4 HS1 HS4-HS8 = PAD
J1 = CON7_6
J2 = STRIP_5X2: CONN HEADER 10POS DUAL .050" PTH; DESCR: HDR 2X5; Part Number: HEADER_1.27MM_VERT_PTH_5X2; Part Type: Berg Unshrouded
J4 = HEADER_9_8
J5 = HEADER_9_12
J6 = HEADER_9_3
J7 = HEADER_9_4
LED1-LED3 = LED-0603-LTST-C190GKT_0: AtherosDescription: DIO,LED,GREEN CLEAR,0603,SMD; CISPartType: Diodes\LED
Q5 Q6 Q8 Q11 Q12 Q14 Q16 = MOSFET_N_0
R22 R24 R25 R90 R132 R137 R138 R161-R164 R168 R169 R173 R175 R176 R179 R180 R213 R216-R218 R220-R224 R226-R228 R230-R234 R241 R251 R252 R254 R255 R264 R266 R270 R670-R677 = R
R170-R172 R174 R177 R184-R186 R219 R225 R258 R261-R263 = RES: ATHEROS KEY: 051-103RJ-000; AtherosDescription: RES,0402,10K OHMS,+/-5%,1/16W; CISPartType: Resistor\0402; Tolerance: +/-5%; WATTAGE: 1/16W
R178 R182 R189 = RES: ATHEROS KEY: 051-104RF-000; AtherosDescription: RES,0402,100K OHMS,+/-1%,1/16W; CISPartType: Resistor\0402; Tolerance: +/-1%; WATTAGE: 1/16W
R181 R188 R195 R196 R198 R636 = RES: ATHEROS KEY: 051-102RJ-000; AtherosDescription: RES,0402,1K OHMS,+/-5%,1/16W; CISPartType: Resistor\0402; Tolerance: +/-5%; WATTAGE: 1/16W
S1 S503 = SW_PUSHBUTTON_2
TP18-TP52 TP54-TP57 TP59 TP76 TP77 = TP
U14 U15 = NTB0104_4
U17 = 76160_13
Y5 = CRY_SM_24MHz_4P_0
C148 C798 = CAP_NP_7
C152 = CAP_NP_11
C153 C799 = CAP_NP_10
C178 = CAP_NP_15
C179 C797 = CAP_NP_6
C180 C791 = CAP_NP_5
C181 = CAP_NP_12
C182 C792 = CAP_NP_1
C183 C796 = CAP_NP_4
C184 = CAP_NP_14
C185 C801 = CAP_NP_8
C186 C793 = CAP_NP_9
C187 C189 C239 C242 C288-C293 = CAP: ATHEROS KEY: 030-104CK-001; AtherosDescription: CAP,0201,X5R,0.1UF,+/-10%,6.3V; CISPartType: Capacitor\0201; StandardCost-100K: 0; Tolerance: +/-20%; URL: 0; VendorDescription: CAP, MLCC, X5R, 0.1uF +/-10%, 10V, 0402, 7"T+R; VendorName: Yageo; VendorPartNumber: CC0402KRX5R6BB104; Voltage: 6.3V
C190 = CAP_NP_13
C191 C794 = CAP_NP_3
C192 C800 = CAP_NP_2
C193 = CAP_SM
J8 = CON-USB-A-4SHD_10: ATHEROS KEY: 140-00111-000; AtherosDescription: CON,USB RT TYPE B, 4P; CISPartType: Connectors\Thru_Hole
R265 = RES: ATHEROS KEY: 053-000RJ-000; AtherosDescription: RES,0805,0 OHMS,+/-5%,1/8W; CISPartType: Resistor\0805; Tolerance: +/-5%; WATTAGE: 1/8W
U4 = SM331-48QFP_0
U11 = AU6350_JGL_48Pin__1
U12 = MIC2526-2BM_0
Y4 Y8 = ZTA_0
C44 = CAP_POL: ESR: ESR < 0.7 Ohm; Type: TANT
C162 = CAP: ATHEROS KEY: 031-104CK-022; AtherosDescription: CAP,0402,X7R,0.1uF,+/-10%,10V; CISPartType: Capacitor\0402; Tolerance: +/-10%; Voltage: 10V
C165 = CAP: ATHEROS KEY: 031-104CK-002; AtherosDescription: CAP,0402,X5R,0.1uF,+/-10%,10V; CISPartType: Capacitor\0402; StandardCost-100K: 0; Tolerance: +/-10%; URL: 0; VendorName: Murata; VendorPartNumber: GRM188F51A105ZA01D; Voltage: 10V
C167 = CAP: ATHEROS KEY: 031-103CK-004; AtherosDescription: CAP,0402,X7R,0.01uF,+/-10%,25V; CISPartType: Capacitor\0402; Tolerance: +/-10%; Voltage: 25V
C168 C171 = CAP: ATHEROS KEY: 033-226CM-001; AtherosDescription: CAP,0805,X5R,22uF,+/-20%,6.3V; CISPartType: Capacitor\0805; Tolerance: +/-20%; Voltage: 16V
D2 = TRANSIL
J3 = CON-USB-A-4SHD_10_v2: ATHEROS KEY: 140-00111-000; AtherosDescription: CON,USB RT TYPE B, 4P; CISPartType: Connectors\Thru_Hole
L23 = IND: ATHEROS KEY: 078-100LM-000; AtherosDescription: IND,SMT,SHIELDING CHOKE,10uH,7.3x7.3; CISPartType: Inductor\Ferrite
LED5 = LED-0603-LTST-C190GKT_10: AtherosDescription: DIO,LED,GREEN CLEAR,0603,SMD; CISPartType: Diodes\LED
Q3 = RT8250_1: ATHEROS KEY: 170-00178-000; AtherosDescription: REG,RT8250,23V,3A,340 kHz STEP-DOWN CONV,SO; CISPartType: IC\Regulator
R91 = RESISTOR
R166 R167 R666 = RES: ATHEROS KEY: 051-000RJ-000; AtherosDescription: RES,0402,0 OHMS,+/-5%,1/16W; CISPartType: Resistor\0402; Tolerance: +/-5%; WATTAGE: 1/16W
R183 = RES: ATHEROS KEY: 051-302RJ-000; AtherosDescription: RES,0402,3K OHMS,+/-5%,1/16W; CISPartType: Resistor\0402; Tolerance: +/-5%; WATTAGE: 1/16W
R190 = RES: ATHEROS KEY: 051-243RF-000; AtherosDescription: RES,0402,24K OHMS, +/-1%,1/16W; CISPartType: Resistor\0402; Tolerance: +/-1%; WATTAGE: ?
R192 = RES: ATHEROS KEY: 051-9312F-000; AtherosDescription: RES,0402,9.31K OHMS,+/-1%,1/16W; CISPartType: Resistor\0402; Tolerance: +/-1%; WATTAGE: ?
S3 = SW_PUSHBUTTON_4
U2 = AU6350_JGL_48Pin__0
U10 = MX25L3205D-8SOP: AtherosDescription: IC,Memory,MX25L6405DZNI-12G,64M-bit SPI FLASH, SO8; CISPartType: IC\Memory
C20-C22 C25 = CAP: ATHEROS KEY: 031-100CJ-000; AtherosDescription: CAP,0402,NPO,10pF,+/-5%,50V; CISPartType: Capacitor\0402; Tolerance: +/-5%; Voltage: 50V
C23 C24 C29-C35 C51 C52 C54 C55 C790 = C_13: +80%-20%; Class: DISCRETE; Colay_Alternate: N/A; Colay_Group: N/A; Component_Name: CAP 0.1UF/16V (0402) Y5V (104); Critical_Part: N; Database_Update: 2005/6/10; Device: c0402; Manufacture: DARFON,PHYCOMP,SAMSUNG,TAIYO; Optional: N/A; Package_Type: SMD; Part Number: 11-034310410; Part Type: 11CAPACITOR\CAP; QVL_Approve: N; Sourcer: ¡¦??paU(P9447); Status: All ?OA3Au¢DyAv0010; Subsystem_ID: N/A; Vendor: ¢DI|t; metal_fabrication: 10111111
C784 = CAP: ATHEROS KEY: 031-105CK-000; AtherosDescription: CAP,0402,X5R,1uF +/-10%,6.3V; CISPartType: Capacitor\0402; Tolerance: +/-10%; Voltage: 6.3V
D11 = LED: BRT; Class: DISCRETE; Colay_Alternate: N/A; Colay_Group: N/A; Component_Name: LED GREEN 3¦Õ BL-B2141U-LC3.2; Critical_Part: N; Data_Sheet: K:\DataSheet\07-DISCRETE\07-015111411.pdf; Database_Update: 2004/11/16; Device: led_d_2p_100_bd157; Electric_SPE: 20mA/2.6V; Manufacturer: BRT; Mode: A7S8X-MX                      ,A8N-E PREMIUM                 ,A8NE-M; Optional: N/A; Package_Type: DIP; Part Number: 07-015111411; Part Type: 07DISCRETE\LED; QVL_Approve: N; Sourcer: ÁÖÌ©ÄÐ  (P7430); Status: All ½¨×hƒžÏÈ™à1; Subsystem_ID: N/A; Vendor: Îå¾ù; metal_fabrication: Ÿo/Ÿo/Ÿo/Ÿo/Ÿo/Ÿo
L2 L3 = BEAD_0: 10 OHM 100MHZ B TYPE MURATA; Class: DISCRETE; Colay_Alternate: N/A; Colay_Group: N/A; Component_Name: FERRITE BEAD (0603) 500mA; Critical_Part: N; Data_Sheet: K:\DataSheet\09-INDUCTOR\09-013010400.pdf; Database_Update: 2004/11/16; Electric_SPE: Irat=500mA; Manufacturer: MURATA; Mode: A2C MAIN_BD./AS               ,A2C MAIN_BD./TG               ,A2D MAIN_BD./AS; Optional: N/A; Package_Type: SMD; Part Number: 09-013010400; Part Type: 09INDUCTOR\INDUCTOR; QVL_Approve: N; Sourcer: ÖÜ¾ý°²  (P0000); Status: All ½¨×hƒžÏÈ™à4; Subsystem_ID: N/A; Vendor: Îå¾ù; metal_fabrication: Ÿo/Ÿo/Ÿo/Ÿo/Ÿo/Ÿo
L4 = INDUCTOR
R16 = r_0: 5%; Class: DISCRETE; Colay_Alternate: N/A; Colay_Group: N/A; Component_Name: RES  22 OHM 1/10W (0603); Critical_Part: N; Database_Update: 2004/11/16; Device: R0603; Electric_SPE: 1/16W; Manufacturer: COMPSTARS           ,PHYCOMP             ,RALEC               ,ROYAL               ,SEI                 ,TA-I TECH           ,; Optional: N/A; Package_Type: SMD; Part Number: 10-003402200; Part Type: 10RESISTOR\RESISTOR; QVL_Approve: N; Sourcer: …Çìo·¼  (P7536); Subsystem_ID: N/A; Tolerance: 5%; Vendor: Ì¨ž³¸ªÎÝ; metal_fabrication: Ÿoæk////Ÿo
R17 = R: 5%; Class: DISCRETE; Colay_Alternate: N/A; Colay_Group: N/A; Component_Name: RES 4.7K OHM 1/10W(0603); Critical_Part: N; Database_Update: 2004/11/16; Device: r0603; Electric_SPE: 1/16W; FPLIST: r0603,syn_r0603,sy-r0603; Manufacturer: COMPSTARS           ,PHYCOMP             ,RALEC               ,ROYAL               ,SEI                 ,TA-I TECH           ,; Modify_Data: 2004/8/7; Optional: N/A; Package_Type: SMD; Part Number: 10-003404720; Part Type: 10RESISTOR\RESISTOR; QVL_Approve: N; Sourcer: …Çìo·¼  (P7536); Subsystem_ID: N/A; Tolerance: 5%; Vendor: Ì¨ž³¸ªÎÝ; metal_fabrication: Ÿoæk////Ÿo
R18 R77 = r_0: 5%; Class: DISCRETE; Colay_Alternate: N/A; Colay_Group: N/A; Component_Name: RES  22 OHM 1/10W (0603); Critical_Part: N; Database_Update: 2004/11/16; Electric_SPE: 1/16W; Manufacturer: COMPSTARS           ,PHYCOMP             ,RALEC               ,ROYAL               ,SEI                 ,TA-I TECH           ,; Optional: N/A; Package_Type: SMD; Part Number: 10-003402200; Part Type: 10RESISTOR\RESISTOR; QVL_Approve: N; Sourcer: …Çìo·¼  (P7536); Subsystem_ID: N/A; Tolerance: 5%; Vendor: Ì¨ž³¸ªÎÝ; metal_fabrication: Ÿoæk////Ÿo
R19 = r_1: 1%; Class: DISCRETE; Colay_Alternate: N/A; Colay_Group: N/A; Component_Name: RES 2.49K OHM 1/10W(0603); Critical_Part: N; Database_Update: 2004/11/16; Device: R0603; Electric_SPE: 1/16W; Manufacturer: COMPSTARS           ,PHYCOMP             ,RALEC               ,ROYAL               ,SEI                 ,TA-I TECH           ,; Optional: N/A; Package_Type: SMD; Part Number: 10-003412429; Part Type: 10RESISTOR\RESISTOR; QVL_Approve: N; Sourcer: …Çìo·¼  (P7536); Subsystem_ID: N/A; Tolerance: 1%; Vendor: Ì¨ž³¸ªÎÝ; metal_fabrication: Ÿoæk////Ÿo
R28 = r_10: 5%; Class: DISCRETE; Colay_Alternate: N/A; Colay_Group: N/A; Component_Name: RES 300 OHM 1/10W (0603); Critical_Part: N; Database_Update: 2004/11/16; Device: R0603; Electric_SPE: 1/16W; Manufacturer: COMPSTARS           ,PHYCOMP             ,RALEC               ,ROYAL               ,SEI                 ,TA-I TECH           ,; Optional: N/A; Package_Type: SMD; Part Number: 10-003403010; Part Type: 10RESISTOR\RESISTOR; QVL_Approve: N; Sourcer: …Çìo·¼  (P7536); Subsystem_ID: N/A; Tolerance: 5%; Vendor: »ÝÙQ; metal_fabrication: Ÿoæk////Ÿo
R31-R45 R69 R70 = R: 1%; Class: DISCRETE; Colay_Alternate: N/A; Colay_Group: N/A; Component_Name: RES 10K OHM 1/10W (0603); Critical_Part: N; Database_Update: 2004/11/16; Device: r0603; Electric_SPE: 1/16W; FPLIST: r0603,syn_r0603,sy-r0603; Manufacturer: COMPSTARS           ,PHYCOMP             ,RALEC               ,ROYAL               ,SEI                 ,TA-I TECH           ,; Modify_Data: 2004/7/28; Optional: N/A; Package_Type: SMD; Part Number: 10-003411030; Part Type: 10RESISTOR\RESISTOR; QVL_Approve: N; Sourcer: …Çìo·¼  (P7536); Subsystem_ID: N/A; Tolerance: 1%; Vendor: Îå¾ù; metal_fabrication: Ÿoæk////Ÿo
R103-R105 R109 = RES: ATHEROS KEY: 051-49R9F-000; AtherosDescription: RES,0402,49.9 OHMS,+/-1%,1/16W; CISPartType: Resistor\0402; Tolerance: +/-1%; WATTAGE: 1/16W
R669 = R_0
T2 = RB1-125BHQ1A_2
U3 = F2e-32_11
Y6 = CRY_SM_24MHz_4P_2
ANT2 = R_1
C73 = CAP: ATHEROS KEY: 031-010CC-000; AtherosDescription: CAP,0402,NPO,1pF,+/-0.25pF,50V; CISPartType: Capacitor\0402; Tolerance: +/-0.25PF; Voltage: 50V
FL1 = MM8130-2600_0
L519 = IND: ATHEROS KEY: 070-4R7LC-100; AtherosDescription: IND,0201,FILM,4.7nH,+/-0.2nH; CISPartType: Inductor\0201; Tolerance: +/-0.2nH
LED8 = LED-0603-LTST-C190GKT_6: AtherosDescription: DIO,LED,GREEN CLEAR,0603,SMD; CISPartType: Diodes\LED
TP58 = TP_0
U16 = MX25L3205D-8SOP_4: AtherosDescription: IC,Memory,MX25L6405DZNI-12G,64M-bit SPI FLASH, SO8; CISPartType: IC\Memory
U18 = 76160_12
Y7 = CRY_SM_24MHz_4P_1
U19 = IC_AU6259-JBF_QFN_28P

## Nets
1V8: C242.Pin1 U18.A4(VREG_OUT_HV)
3.3V: LED7.1(ANODE) R188.2(Pin2)
AVDD33: C31.2 C55.2 L3.2 U3.14(AVDD33)
AVDDL: C29.1 C30.2 C54.2 L2.1 U3.6(AVDDL) U3.11(AVDDL) U3.17(AVDDL)
DVDDL: C32.2 C34.2 C35.2 L2.2 L4.1 U3.38(DVDDL)
GND: ANT2.1 C20.2(Pin2) C21.2(Pin2) C22.2(Pin2) C23.1 C24.1 C25.2(Pin2) C29.2 C30.1 C31.1 C32.1 C33.2 C34.1 C35.1 C44.2 C51.1 C52.1 C54.1 C55.1 C73.2(Pin2) C147.2 C148.1 C149.2 C150.2 C151.2 C152.2 C153.2 C154.1(Pin1) C155.2 C156.2 C157.2(Pin2) C158.1(Pin1) C159.2(Pin2) C160.1(Pin1) C161.2 C162.2(Pin2) C163.2 C164.2 C165.2(Pin2) C166.2(Pin2) C168.2(Pin2) C169.2(Pin2) C171.2(Pin2) C172.2(Pin2) C176.2(Pin2) C177.2(Pin2) C178.2 C179.2 C180.2 C181.2 C182.2 C183.2 C184.2 C185.2 C186.2 C187.Pin2 C189.Pin2 C190.1 C191.2 C192.1 C193.2 C239.Pin2 C240.2(Pin2) C241.2(Pin2) C242.Pin2 C284.2 C285.2(Pin2) C286.2(Pin2) C287.2(Pin2) C288.Pin2 C289.Pin2 C290.Pin2 C291.Pin2 C292.Pin2 C293.Pin2 C294.2(Pin2) C773.2(Pin2) C774.2(Pin2) C784.2(Pin2) C785.2(Pin2) C790.1 C791.2 C792.2 C793.2 C794.2 C795.2 C796.2 C797.1 C798.1 C799.2 C800.1 C801.1 D2.1(ANODE) D11.2(CATHODE) FL1.1(GND) FL1.3(GND) HS1.1 HS4.1 HS5.1 HS6.1 HS7.1 HS8.1 J1.6 J2.3 J2.5 J2.9 J3.5(GND) J3.6(GND) J3.7(GND) J3.8(GND) J3.9(GND) J4.GND@3(GND) J5.GND@1(GND) J5.GND@2(GND) J8.4(GND) J8.5(G) J8.6(G) J8.7(G) J8.8(G) J9.P42(MII_TXD2) J9.P62(GND) J9.P63(GND) J9.P64(GND) J9.P65(GND) J9.P66(GND) LED5.2(CATHODE) Q3.1(GND) Q5.3(S) Q8.3(S) Q12.3(S) Q14.3(S) Q16.3(S) R19.1 R32.2 R34.2 R36.2 R38.2 R40.2 R42.2 R44.2 R69.2 R174.1(Pin1) R176.1 R177.1(Pin1) R183.1(Pin1) R192.1(Pin1) R213.1 R216.2 R219.1(Pin1) R227.2 R231.2 R235.2(Pin2) R253.2(Pin2) R258.1(Pin1) R269.2(Pin2) R671.2 R675.2 R676.2 S1.3 S1.4 S3.2 S3.4 S503.3 S503.4 T2.1(CH1) T2.2(CH2) TP21.1(.) TP37.1(.) TP52.1(.) TP58.2(.) U2.2(GND) U2.25(G) U3.36(TXD2) U3.41(GND) U4.C4(Vssq) U4.E7(Vss) U4.G5(Vss) U4.H10(Vss) U4.K8(Vss) U4.N2(Vssq) U4.N5(Vssq) U4.P4(Vssq) U4.P6(Vssq) U10.4(GND) U11.3(PVSS) U11.15(PLL_VSS) U11.40(VSSH) U12.2(GND) U14.6(GND) U15.6(GND) U16.1(NC/A0) U16.2(NC/A1) U16.3(NC/A2) U16.4(VSS) U16.7(WP) U16.9(G) U17.5(GNDANA) U17.18(GND1) U17.35(GND2) U17.42(GND3) U17.49(G) U18.A1(VSS_AUX) U18.C1(VSS_RADIO) U18.C4(CSS_DIG) U19.1(VSSH) U19.12(PVSS) U19.26(VSS) U19.DiePad(GND) Y4.2 Y4.4 Y6.2 Y6.4 Y7.2 Y7.4 Y8.2 Y8.4
V18: C796.1 U19.16(V18) U19.20(VDD) U19.25(VDD)
V33: C791.1 C792.1 C793.1 C794.1 C795.1 C797.2 R670.2 U19.4(AVDD) U19.7(AVDD) U19.9(PVDD) U19.15(AVDD) U19.18(V33) U19.28(VDDH)
VCC: C186.1 C187.Pin1 Q6.3(S) Q11.2(D) R218.1 R222.1 R225.2(Pin2) R228.1 R229.1(Pin1) R265.Pin2 R672.1 R673.1 R677.2 U12.1(VIN)
VCC1.8: C181.1 C182.1 C183.1 U11.13(V18) U11.14(PLL_VDD) U11.18(VDD) U11.26(VDD)
VCC3.3: C178.1 C179.1 C180.1 C184.1 R217.1 R221.2 R223.1 R224.2 U11.6(AVDD) U11.9(AVDD) U11.16(VDDH) U11.39(VDDH) U11.43(AVDD) U11.46(AVDD) U11.48(PVDD)
VDD5_USB: C150.1 C151.1 C155.1 C164.1 D5.A(ANODE) R22.2 R164.1 R253.1(Pin1) TP23.1(.) U2.8(VBUS)
VDD5V: C168.1(Pin1) C169.1(Pin1) C171.1(Pin1) C189.Pin1 D5.C(CATHODE) D6.C(CATHODE) J1.2 J5.5V J5.IOREF Q3.3(VIN) Q11.3(S) R189.Pin2 R214.1(Pin1) R262.2(Pin2) R263.2(Pin2) R265.Pin1
VDD25_AR934X: C157.1(Pin1) C159.1(Pin1) J9.P30(VDD25_AR934X) J9.P31(VDD25_AR934X) J9.P32(VDD25_AR934X) LED4.1(ANODE) LED6.1(ANODE) R91.2 R180.1 R186.Pin1 U14.1(VCCA) U15.1(VCCA)
VDD33: C44.1 C158.2(Pin2) C160.2(Pin2) C172.1(Pin1) C240.1(Pin1) C241.1(Pin1) C285.1(Pin1) C287.1(Pin1) D4.A(ANODE) J2.1 J9.P19(VDD33) J9.P20(VDD33) J9.P21(VDD33) J9.P22(VDD33) J9.P23(VDD33) J9.P24(VDD33) J9.P25(VDD33) J9.P26(VDD33) J9.P27(VDD33) J9.P28(VDD33) L23.2 R25.2 R161.1 R162.1 R163.1 R170.2(Pin2) R171.2(Pin2) R172.2(Pin2) R184.2(Pin2) R190.2(Pin2) TP38.1(.) TP59.1(.) U14.11(VCCB) U15.11(VCCB) U17.6(VDDANA) U17.17(VDDIO1) U17.36(VDDIO2) U17.44(VDDIN)
VDD_CT: C784.1(Pin1) C785.1(Pin1) R666.2(Pin2) T2.R3(CT)
VDDCORE: C286.1(Pin1) U17.43(VDDCORE1)
VDDH: C33.1 R16.1 R41.2 R45.2 R70.2 R666.1(Pin1) U3.8(VDDH_REG)
VDDIO_RGMII: C23.2 C24.2 R16.2 R31.2 R33.2 R35.2 R37.2 R39.2 R43.2 U3.27(VDDIO_REG)
VIN: C156.1 C163.1 D6.A(ANODE) J5.VIN R269.1(Pin1)
BLE_USB_DN: R252.1 U19.5(DP1_DM)
BLE_USB_DP: R251.1 U19.6(DP1_DP)
BLE_VDD33: C239.Pin1 C293.Pin1 LED8.1(ANODE) R179.2 R241.2 U16.8(VCC) U18.A5(VREG_EN_RST#) U18.B4(VREG_IN_HV) U18.C3(VDD_PADS) U18.C6(VDD_HOST)
BUS_PWR: R670.1 R671.1 U19.19(BUS_PWREDN)
BUS_PWRED: R221.1 U11.17(BUS_PWREDN)
CARDDATA0: R138.1 U4.M5(CMD) U11.27(ARDDATA0)
CARDDATA4: U4.A3(DAT0) U11.31(ARDDATA4)
CARDDATA5: U4.A4(DAT1) U11.32(ARDDATA5)
CARDDATA6: U4.A5(DAT2) U11.33(ARDDATA6)
CARDDATA7: U4.B2(DAT3) U11.34(ARDDATA7)
CARDDATA8: U4.B3(DAT4) U11.35(ARDDATA8)
CARDDATA9: U4.B4(DAT5) U11.36(ARDDATA9)
CARDDATA10: U4.B5(DAT6) U11.37(ARDDATA10)
CARDDATA11: U4.B6(DAT7) U11.38(ARDDATA11)
ChipResetN: R230.2 U11.21(ChipResetN)
ChipResetN_1: R674.2 U19.27(ChipResetN)
CONTROLOUT0: R132.1 R220.2
D21_RESET: C147.1 J2.10 R161.2 R198.1(Pin1) R266.2 R270.2 S1.1 S1.2
D21_RXD: R254.2 U17.38(PB23)
D21_TXD: R255.2 U17.37(PB22)
D-: J3.2(DATA-) R166.1(Pin1) TP26.1(.)
DGI_GPIO2: J4.8 U17.11(PA6)
DGI_GPIO3: J4.9 U17.12(PA7)
DP1_DM: R233.1 TP50.1(.) U11.44(USB1_DM)
DP1_DP: R234.1 TP51.1(.) U11.45(USB1_DP)
DP1_OVRCUR: R223.2 U11.20(DP1_OVRCUR) U12.4(FAULT/)
DP1_PWR: C193.1 R222.2 R232.1 TP49.1(.) U12.5(VOUT)
DP1_PWRUP: R226.2 U11.19(DP1_PWRUP)
DP1_PWRUP (page 09_AU6259): R672.2 U19.21(DP1_PWRUP)
DP2_DM: J5.DP2_DM U19.13(DP2_DM)
DP2_DP: J5.DP2_DP U19.14(DP2_DP)
eMMC_VDD33: C152.1 R137.2 R138.2 U4.C6(Vccq) U4.E6(Vcc) U4.F5(Vcc) U4.J10(Vcc) U4.K9(Vcc) U4.M4(Vccq) U4.N4(Vccq) U4.P3(Vccq) U4.P5(Vccq)
ETH_VDD33: C51.2 C52.2 L3.1 R17.2 R669.1 U3.3(VDD33)
GPIO0: J9.P1(GPIO_0) R175.2
GPIO1: J9.P2(GPIO_1) U14.2(A1)
GPIO2: J9.P3(GPIO_2) U14.3(A2)
GPIO3: J9.P4(GPIO_3) U14.4(A3)
GPIO4: J9.P5(GPIO_4) U14.5(A4)
GPIO13: J9.P14(GPIO_13) U15.3(A2)
GPIO14: J9.P15(GPIO_14) U15.4(A3)
GPIO15: J9.P16(GPIO_15) R174.2(Pin2) R177.2(Pin2) U14.12(OE) U15.12(OE)
GPIO16: J9.P17(GPIO_16) U15.2(A1)
GPIO17: J9.P18(GPIO_17) R182.2(Pin2)
GTX_CLK: J9.P45(GTX_CLK) R77.2
HANDSHAKE: J7.7 R178.2(Pin2) U17.30(PA21)
INT: R45.1 TP41.1(.) U3.20(INT)
LED_10_100: TP44.1(.) U3.24(LED_10_100)
LED_1000: R69.1 R70.1
LED_ACT: R28.1 R41.1 R42.1 U3.21(LED_ACT)
LX: L4.2 U3.2(LX)
MII_MDC: J9.P39(MII_MDC) U3.40(MDC)
MII_MDIO: J9.P37(MII_MDIO) R17.1 U3.39(MDIO)
MII_RX_CLK: J9.P51(MII_RX_CLK) R18.1 R39.1 R40.1
MII_RX_DV: J9.P50(MII_RX_DV) R43.1 R44.1 U3.30(RX_DV)
MII_RXD0: J9.P46(MII_RXD0) R31.1 R32.1 U3.29(RXD0)
MII_RXD1: J9.P52(MII_RXD1) R33.1 R34.1 U3.28(RXD1)
MII_RXD2: J9.P53(MII_RXD2) R35.1 R36.1 U3.26(RXD2)
MII_RXD3: J9.P55(MII_RXD3) R37.1 R38.1 U3.25(RXD3)
MII_TX_EN: J9.P44(MII_TX_EN) U3.32(TX_EN)
MII_TXD0: J9.P40(MII_TXD0) U3.34(TXD0)
MII_TXD1: J9.P41(MII_TXD1) U3.35(TXD1)
MII_TXD3: J9.P43(MII_TXD3) U3.37(TXD3)
MISO: J4.12 U14.8(B3) U17.28(PA19)
MOSI: J4.11 U14.9(B2) U17.25(PA16)
PA0_XIN32: C161.1 U17.1(PA0) Y5.2
PA1_XOUT32: C284.1 U17.2(PA1) Y5.1
PA02_AIN0: J6.A0 U17.3(PA2)
PA03_AREFA: C154.2(Pin2) C294.1(Pin1) J4.AREF U17.4(PA3)
PA04_AIN4: J6.A3 U17.9(PA4)
PA05_AIN5: J6.A4 U17.10(PA5)
PA08_TCC0-W0: J7.2 U17.13(PA8)
PA09_TCC0-W1: J7.3 U17.14(PA9)
PA10_TCC0-W2: J7.1(1(TX0)) U17.15(PA10)
PA11_TCC0-W3: J7.0(0(RX0)) U17.16(PA11)
PA14_TCC0-W4: J7.4 U17.23(PA14)
PA15_TCC0-W5: J7.5 U17.24(PA15)
PA20_TCC0-W6: J7.6 U17.29(PA20)
PA27_TX_LED: LED2.2(CATHODE) U17.39(PA27)
PA28_PM: R261.1(Pin1) U17.41(PA28)
PA30_SWCLK: R196.2(Pin2) U15.8(B3) U17.45(PA30)
PA31_SWDIO: R195.2(Pin2) U15.9(B2) U17.46(PA31)
PB02_AIN10: J6.A5 U17.47(PB2)
PB03_RX_LED: LED1.2(CATHODE) U17.48(PAPB3)
PB08_AIN2: J6.A1 U17.7(PB8)
PB09_AIN3: J6.A2 U17.8(PB9)
PB10_S4_SPI_MOSI: J1.4 TP22.1(.) U17.19(PB10)
PB11_S4_SPI_SCK: J1.3 TP18.1(.) U17.20(PB11)
PB12_S4_SPI_MISO: J1.1 TP19.1(.) U17.21(PA12)
PHY_RSTn: C790.2 Q14.2(D) R669.2 TP43.1(.) U3.1(RSTn)
PIO1: R215.2(Pin2) U18.E4(PIO[1])
RBIAS: R19.2 U3.7(RBIAS)
RESET_B: J9.P33(RESET_B)
RREF: R675.1 U19.8(UP_RREF)
RST_B: C165.1(Pin1) R90.2 R186.Pin2 S503.1 S503.2
SCK: J4.13 Q8.1(G) U14.7(B4) U17.26(PA17)
SCL: J4.SCL R163.2 U17.32(PA23)
SDA: J4.SDA R162.2 U17.31(PA22)
SDCDN: R227.1 U11.23(SDCDN)
SPI_CLK: J9.P7(GPIO_6) TP34.1(.) U10.6(SCLK)
SPI_CS_L: J9.P6(GPIO_5) R636.1(Pin1) TP30.1(.) U10.1(\\~{CS})
SPI_MI_SO: J9.P9(GPIO_8) R181.1(Pin1) R183.2(Pin2)
SPI_MO_SI: J9.P8(GPIO_7) TP36.1(.) U10.5(SI/SIO0)
SS: J4.10 U14.10(B1) U17.27(PA18)
SUSP/RI_SCI: R173.2 U17.22(PA13)
TARGET_RESET_EDBG: J1.5 J5.RESET Q5.2(D) R198.2(Pin2) TP20.1(.) U17.40(RESETN)
TARGET_USB_N: TP76.1(.) U11.7(DP3_DM) U17.33(PA24)
TARGET_USB_P: TP77.1(.) U11.8(DP3_DP) U17.34(PA25)
TRXN0: R103.2(Pin2) T2.R2(RD-) U3.10(TRXN0)
TRXN1: R105.2(Pin2) T2.R4(TD-) U3.13(TRXN1)
TRXP0: R104.2(Pin2) T2.R1(RD+) U3.9(TRXP0)
TRXP1: R109.2(Pin2) T2.R5(TD+) U3.12(TRXP1)
UART_RX: R168.2
UART_SIN: J9.P10(GPIO_9)
UART_SOUT: J9.P11(GPIO_10) R169.2
UP_DM: U11.4(DP2_DM) U19.2(UP_DM)
UP_DP: U11.5(DP2_DP) U19.3(UP_DP)
USB+: J9.P47(USB+) TP39.1(.) U11.42(USB_DP)
USB-: J9.P48(USB-) TP40.1(.) U11.41(USB_DM)
USB_LED: J9.P12(GPIO_11) R237.Pin1
WLAN_LED: J9.P13(GPIO_12) R236.Pin1
XSCI: C192.2 U11.2(XSCI) Y4.1
XSCI_1: C801.2 U19.11(XSCI) Y8.1
XSCO: C190.2 U11.1(XSCO) Y4.3
XSCO_1: C800.2 U19.10(XSCO) Y8.3
XTLI: C21.1(Pin1) U3.5(XTLI) Y6.1
XTLO: C20.1(Pin1) U3.4(XTLO) Y6.3
N16905192: C799.1 R673.2 R674.1 R676.1
N17133199: C798.2 R677.1 U19.17(AVDD5V)
N18755880: Q3.4(VFB) R190.1(Pin1) R192.2(Pin2)
N29360222: C185.1 R218.2 U11.11(AVDD5V)
N29360603: C191.1 R228.2 R230.1 R231.1
N29361017: R213.2 U11.47(UP_RREF)
N29361037: R220.1 U11.25(Controlout0)
N29361093: R217.2 U11.10(V33)
N29362718: J8.2(DATA-) R233.2
N29362720: J8.3(DATA+) R234.2
N29367184: TP46.1(.) U11.28(ARDDATA1)
N29367186: TP45.1(.) U11.30(ARDDATA3)
N29367202: R216.1 U11.29(ARDDATA2)
N29446768: TP47.1(.) U11.24(Controlout1)
N29446793: R224.1 TP48.1(.) U11.22(MSINS)
N29535449: J8.1(VCC) R232.2
N29628452: Q6.2(D) U12.3(ENABLE)
N29628945: Q6.1(G) R225.1(Pin1) R226.1
N29680703: Q5.1(G) R175.1 R176.2
N29697820: R178.1(Pin1) U15.10(B1)
N29822034: C162.1(Pin1) R185.1(Pin1) R188.1(Pin1) R636.2(Pin2) TP31.1(.) U10.8(VCC)
N29822147: R185.2(Pin2) TP33.1(.) U10.7(\\~{HOLD})
N29822157: R181.2(Pin2) TP32.1(.) U10.2(SO/SIO1)
N29822179: R184.1(Pin1) TP35.1(.) U10.3(\\~{WP}/ACC)
N29840704: D2.2(CATHODE) R180.2 R182.1(Pin1) S3.1 S3.3
N30243032: J2.2 R195.1(Pin1)
N30243034: J2.4 R196.1(Pin1)
N30245324: R167.2(Pin2) U2.3(D+)
N30245328: J3.3(DATA+) R167.1(Pin1) TP25.1(.)
N30245349: J3.1(VCC) R164.2
N30245904: C166.1(Pin1) D4.C(CATHODE) J5.3V3
N30256931: D11.1(ANODE) R28.2
N30262555: R18.2 U3.31(RX_CLK)
N30262578: R77.1 U3.33(GTX_CLK)
N30264750: C773.1(Pin1) R103.1(Pin1) R104.1(Pin1)
N30264756: C774.1(Pin1) R105.1(Pin1) R109.1(Pin1)
N30270963: R166.2(Pin2) U2.4(D-)
N30271078: R24.1 R25.1 U2.5(VIO) U2.6(VDD)
N30272568: R168.1 U2.21(TX_SCI)
N30272570: R169.1 U2.20(RX_SCI)
N30286499: C25.1(Pin1) U18.A2(XTAL_OUT) Y7.1
N30286504: C22.1(Pin1) U18.A3(XTAL_IN) Y7.3
N30287684: C288.Pin1 U18.D6(VDD_DIG)
N30287731: C289.Pin1 U18.C2(VDD_AUX)
N30287781: C290.Pin1 C291.Pin1 U18.B2(VDD_RADIO)
N30288219: FL1.4(I) U18.B1(BT_RF)
N30288222: C292.Pin1 FL1.2(O) L519.2 TP58.1(.)
N30288539: ANT2.2 L519.1
N30288770: ANT2.3 C73.1(Pin1)
N30294743: R241.1 U16.5(SDA) U18.E5(PIO[4])
N30294746: R179.1 U16.6(SCL) U18.E3(PIO[3])
N30295035: TP24.1(.) U18.C5(PIO[5])
N30295038: R251.2 TP28.1(.) U18.B6(USB_DP)
N30295041: R252.2 TP29.1(.) U18.B5(USB_DN)
N30295511: TP27.1(.) U18.E6(SPI_PCM#_SEL)
N30295514: TP54.1(.) U18.D4(PCM_IN/SPI_MOSI/PIO[21])
N30295552: TP55.1(.) U18.E2(PCM_OUT/SPI_MISO/PIO[22])
N30295555: TP56.1(.) U18.D2(PCM_SYNC/SPI_CS#/PIO[23])
N30295558: TP57.1(.) U18.D3(PCM_CLK/SPI_CLK/PIO[24])
N30297564: C148.2 U4.C2(Vddi)
N30297724: C149.1 R132.2 U4.M6(CLK)
N30297794: C153.1 R137.1 U4.K5(RST)
N30375172: R255.1 U2.12(RX_ECI)
N30375180: R254.1 U2.13(TX_ECI)
N30409568: TP42.1(.) U3.23(CLK_25M)
N30520976: R258.2(Pin2) U15.7(B4)
N30520983: R219.2(Pin2) U15.5(A4)
N30586310: C167.1(Pin1) Q3.6(VBST)
N30586768: Q3.5(EN) R189.Pin1
N30587033: C167.2(Pin2) L23.1 Q3.2(SW)
N30591849: Q12.2(D) R262.1(Pin1) R264.2
N30591912: Q11.1(G) R263.1(Pin1) R264.1
N30604924: Q12.1(G) R261.2(Pin2)
N30690641: LED3.2(CATHODE) Q8.2(D)
N30690822: LED3.1(ANODE) R172.1(Pin1)
N30715950: C176.1(Pin1) C177.1(Pin1) R22.1 R24.2 U2.7(REGIN)
N30739203: R173.1 U2.1(SUSP/RI_SCI)
N30745459: Q14.1(G) Q16.2(D) R91.1
N30745463: Q16.1(G) R90.1
N30746234: LED8.2(CATHODE) R215.1(Pin1)
N30758974: C170.2(Pin2) U2.11(RTS_ECI)
N30780089: LED5.1(ANODE) R214.2(Pin2) R229.2(Pin2)
N30807139: R270.1 U2.15(GPIO0_DTR_ECI)
N30820251: C170.1(Pin1) R266.1
N30854525: LED7.2(CATHODE) R235.1(Pin1)
N30854617: LED4.2(CATHODE) R236.Pin2
N30854719: LED6.2(CATHODE) R237.Pin2
N30862825: LED1.1(ANODE) R170.1(Pin1)
N30862831: LED2.1(ANODE) R171.1(Pin1)

Not connected (* = marked no-connect by the designer): H1 1; H2 1; H4 1; J2 6* 7* 8*; J3 4(ID)*; J5 NC*; T2 L1(L1Y+)* L2(L2Y-)* L3(L3G+)* L4(L4G-)* R7(RXCT)* R8(TXCT)* R9(SPARE1)* R10(SPARE2)*; U2 9(RST) 10(CTS_ECI) 14(GPIO1_DSR_ECI) 16(DCD_ECI) 17(SUSP/RI_ECI) 18(CTS_SCI) 19(RTS_SCI) 22(GPIO2_DSR_SCI) 23(GPIO1_DTR_SCI) 24(GPIO0_DCD_SCI); U3 15(TRXP2)* 16(TRXN2)* 18(TRXP3)* 19(TRXN3)* 22(LED_1000)*; U11 12(SD_V33)*; U18 A6(VREG_IN_USB)* D5(PIO[2])* E1(PIO[0]); U19 22(DP1_OVRCUR)* 23(NC)* 24(SUSPEND)*

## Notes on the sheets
sheet 1
- LED Display Circuit
- Power LED
sheet 2
- Wi-Fi
  Antenna
- CP2105
- RF
- USB
- PC
- USB
- UART
- ttyUSB0
- ttyUSB1
- MIPS 74K CPU
- UART
- GPIO
- Headers
- SWD
- Level
  Translators
- SAMD21G18A
- HANDSHAKE
- Linux Reset Button
- SPI/ICSP
- 16MHz
- Reset
- WLAN RST Button
- USB
- LEDs
- MCU Reset Button
- 12MHz
- USB0
- AU6350
  USB2.0 HUB
  & Card reader
- USB
- USB1
- USB Dongle
- Bluetooth
  (CSR8510)
- USB0
- AU6259 2 port
     USB HUB
- USB2
- USB1
- USB Signal
  on Pin Header
- eMMC 4GB
- Microdog
- 0.1
- Microdog
- 0.4
sheet 3
- dogghoat Power Block Diagram
- VDD33_LDO
- SW_REG_OUT
- VDD33
- 3.3V
- DC/DC
- ON/OFF
- 1.2V
- +1.2V
- VIN
  Selector
- USB OTG
- +3.3V
- MIPS 74k CPU
- Headers
- VIN from Pin Header
- +5V
- +5V
- 2.5V
- LDO25_OUT
- +2.5V
- ATMEGA D21
- eMMC
- GPIO
- ON/OFF
- BLE
- V18_OUT
- HUB
- I-Limit
- USB A
- +1.8V
- V33_OUT
- +3.3V
sheet 4
- SPI Flash
- GPIO configuration button
- WLAN RST
- UART connection
- PUSH BUTTON SWITCHES
- RESET
  ETH PHY
- RESET
  SW
- UART to USB
- LNX-RST
- Micro USB
- Notes:
  Rbot=R192=10K, Rtop=R190=33.2k
  VOUT = 0.765 ( 1 + Rtop/Rbot) V
  Vout = 0.765 ( 1 + 33.2/10) V= 3.3 V
sheet 5
- To RGMII&SMI interface at MAC side
- LED
- Power-on Strapping Pins
- PHY_ADDR[0] (IPD)
- PHY_ADDR[1] (IPD)
- MODE[0] (IPD)
- MODE[1] (IPD)
- 1.8V/1.5V Selection (IPD)
- MODE[3] (IPD)
- MODE[2] (IPU)
- PHY_ADDR[2] (IPU)
- MODE[3:0]:
  1100: RGMII, PLLOFF, INT (Suggested)
  1110: RGMII, PLLON,  INT
sheet 7
- 0:Bus Power
  1:Self Power
- Please close to U1
sheet 8
- ICSP1
- MCU-RST
- AP2302GN
- 2
- D
- 1
- G
- S
- 3
- USB
- uUSB
- RJ45
- SAM D21 LED Control
sheet 9
- Connects with Hornet
- Bypass CAP must
  put near chip U14
- CAP
- CONTROLOUT0, trace length shorter ,
  surround with GND.
- AP2301GN-HF
- 2
- eMMC 153 FBGA
- Over Current Function
- AP2301GN-HF
- 2
- D
- 1
- G
- S
- 3
- Reserve 0 ohm resistor for EMI
  certification
- USB_A Female
- CONTROLOUT1  trace length shorter
  , surround with GND.
